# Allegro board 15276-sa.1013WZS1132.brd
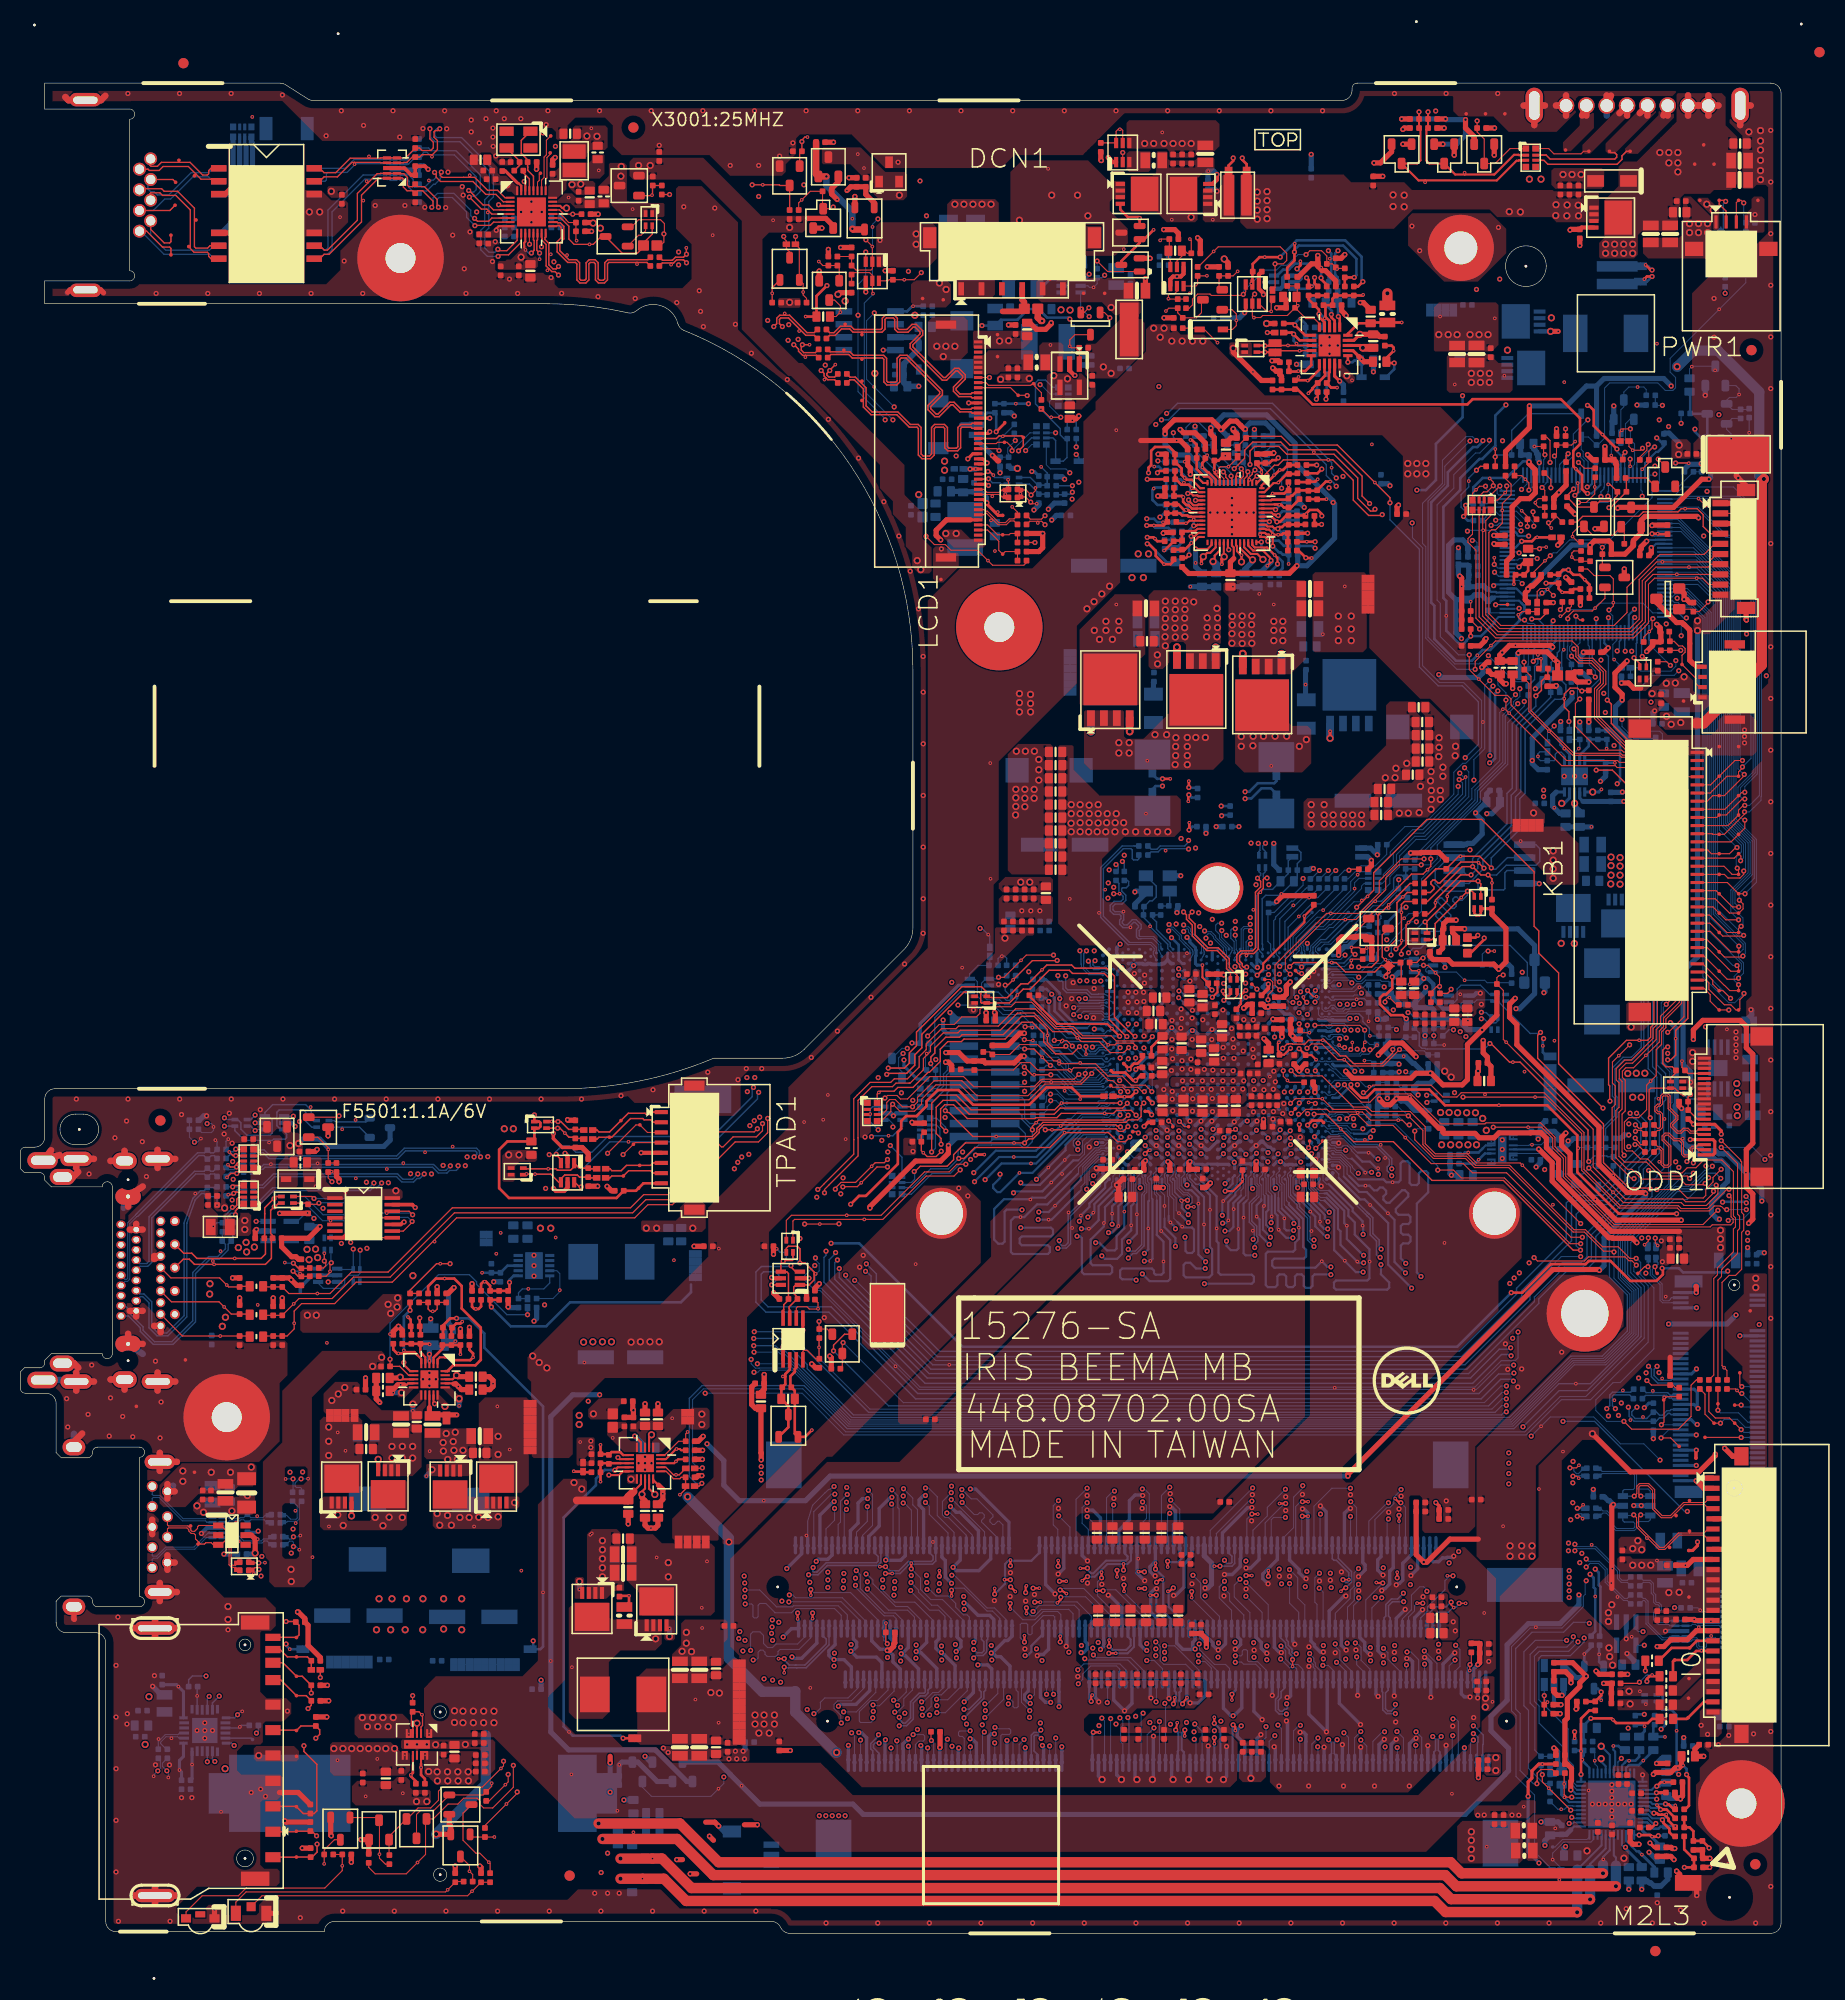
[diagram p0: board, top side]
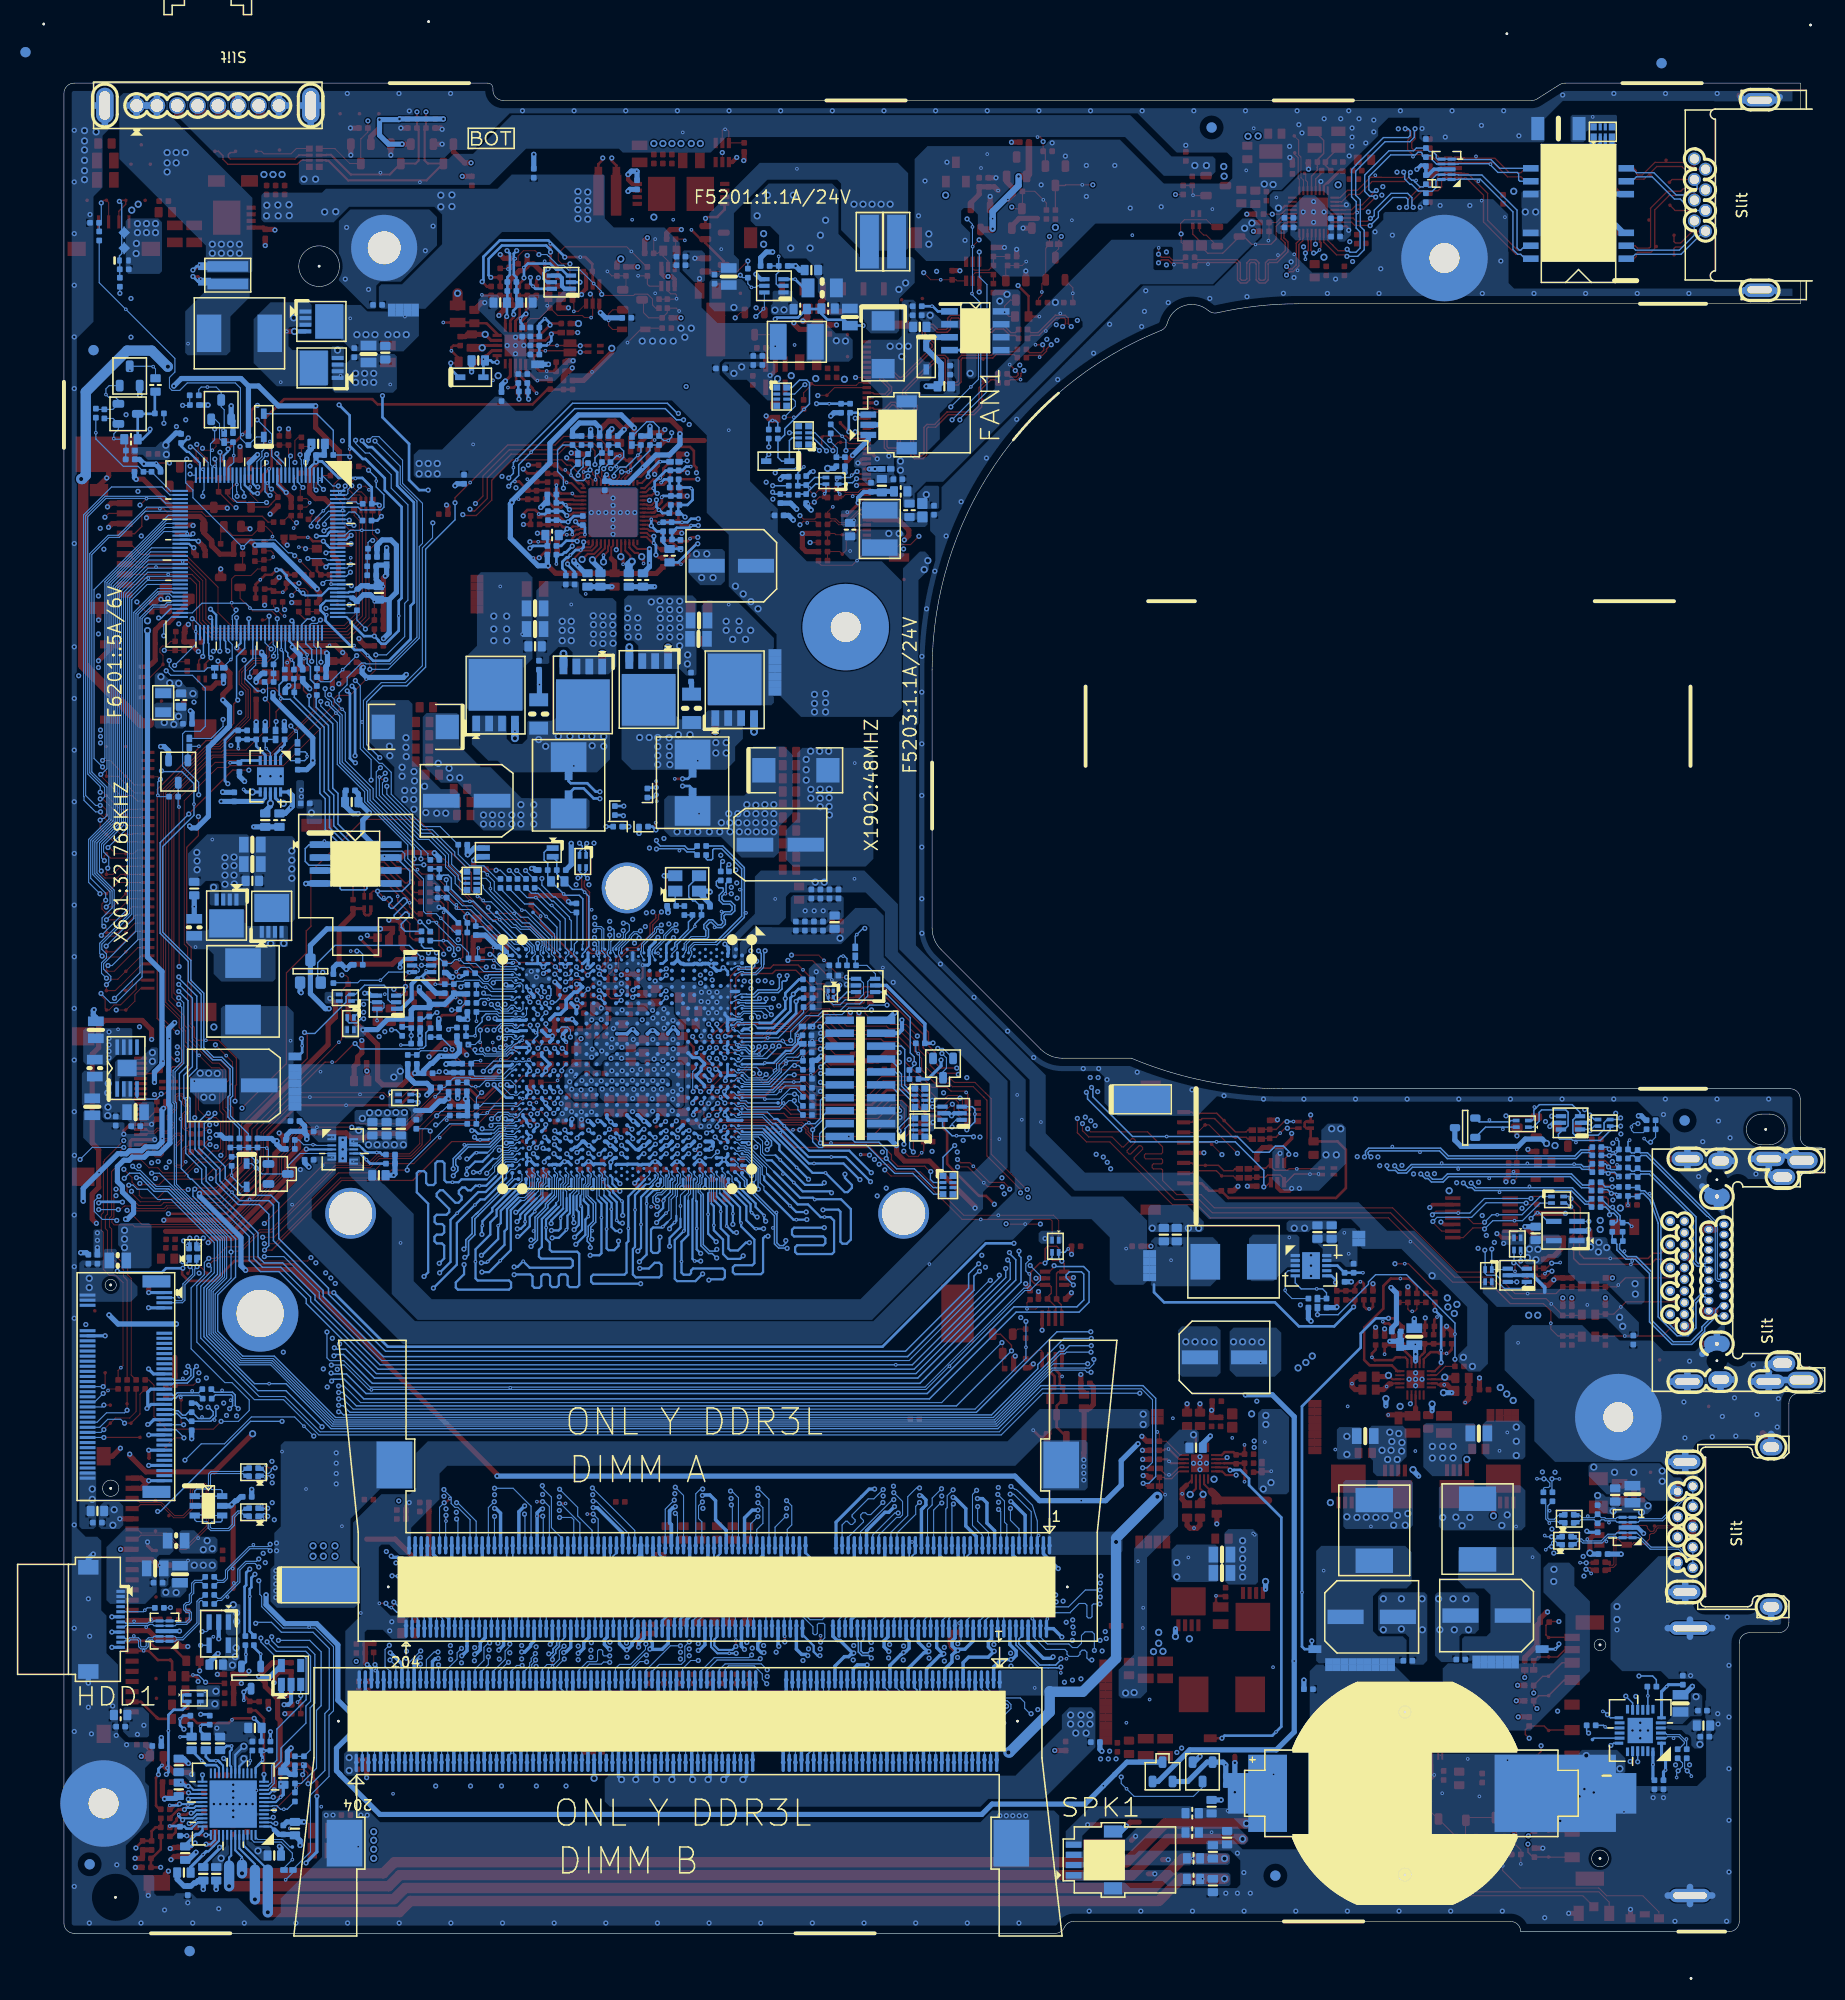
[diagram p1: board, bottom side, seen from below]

Outline 173.2 x 181.97 mm; copper layers: TOP, L2VCC, L3, L4, L5GND, BOTTOM. Coordinates in mm from the lower left corner of the outline.

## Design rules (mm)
constraint set DEFAULT: min track width 0.127, pair gap 0.102
net group APU_4_5: nets H_A20GATE PM_PWRBTN#_R
net group APU_4_8: nets PM_RSMRST# PM_RSMRST#_R
net group CLK: nets CLK_PCI_KBC CLK_PCI_LPC
net group CRT_SYNC_50-MW: nets CRT_HSYNC_CON CRT_VSYNC_CON
net group DDR_RST-MW: nets DDR3_DRAMRST# M_A_EVENT#
net group FAN_TACH: nets FAN_TACH1 FAN_TACH1_C
net group APU_4_12: nets APU_PWROK APU_PWROK_HDT APU_SIC APU_SID H_PROCHOT# H_PROCHOT#_EC PQ4008_6 PQ4405_3 PROCHOT_EC
net group APU_TEST_4: nets APU_TEST0 APU_TEST1 APU_TEST2 APU_TEST6_DIRECRACKMON APU_TEST14_BP0 APU_TEST15_BP1 APU_TEST16_BP2 APU_TEST17_BP3 APU_TEST18_PLLTEST1 APU_TEST19_PLLTEST0 APU_TEST28_H_PLLCHRZ APU_TEST28_L_PLLCHRZ APU_TEST31_M_TEST APU_TEST36_FREE_2 APU_TEST37_FREE_2 BYPASSCLK_H BYPASSCLK_L
net group APU_ZVSS: nets DP_2K_ZVSS DP_150_ZVSS M_ZVDDIO P_RX_ZVDD_095 P_TX_ZVDD_095 SATA_ZVDD_095 SATA_ZVSS USB_RCOMP USB_SS_ZVDD_095 USB_SS_ZVSS
net group AUDIO_BEEP: nets AUD_HP1_JACK_L AUD_HP1_JACK_L1 AUD_HP1_JACK_R AUD_HP1_JACK_R1 AUD_PC_BEEP AUD_PC_BEEP_C AUD_PORTA_L_R_B AUD_PORTA_R_R_B AUD_SENSE AUD_SENSE_A CBN CBP CPVEE HDA_SPKR HDA_SPKR_R JACK_PLUG KBC_BEEP KBC_BEEP_R LINE1-L_C LINE1-L_R LINE1_L LINE1_R LINE1_VREFO_L LINE1_VREFO_R MIC2_VREFO
net group AUDIO_BITCLK-MW: nets CODEC_BITCLK_R HDA_CODEC_BITCLK HDA_CODEC_BITCLK_R
net group AUDIO_DIGITAL-MW: nets CODEC_SDOUT_R HDA_CODEC_RST# HDA_CODEC_RST#_R HDA_CODEC_SDIN0 HDA_CODEC_SDOUT HDA_CODEC_SDOUT_R HDA_CODEC_SYNC HDA_CODEC_SYNC_R HDA_SDIN0
net group CARD_12MIL: nets RREF RSET SDREFG V18
net group CLK-REQ: nets CLK_LAN_REQ0#_R CLK_PCIE_LAN_REQ0# CLK_PCIE_WLAN_REQ1#
net group CR_50OHM-MW: nets SD_CD# SD_CD_R# SD_CLK SD_CLK_5170 SD_CMD SD_D0 SD_D1 SD_D2 SD_D3 SD_WP SD_WP_5170
net group CR_GPIO-MW: nets CR_GPIO0
net group CRT-MW: nets CRT_DDCCLK_CON_R CRT_DDCDATA_CON_R CRT_HSYNC1_1 CRT_VSYNC1_1 DAC_HSYNC DAC_SCL DAC_SDA DAC_VSYNC DAC_ZVSS
net group CRT-RGB-MW: nets DAC_BLUE DAC_GREEN DAC_RED
net group CRT_55-MW: nets CRT_B CRT_G CRT_R
net group DDR3_A_CMD: nets M_A_A0 M_A_A1 M_A_A2 M_A_A3 M_A_A4 M_A_A5 M_A_A6 M_A_A7 M_A_A8 M_A_A9 M_A_A10 M_A_A11 M_A_A12 M_A_A13 M_A_A14 M_A_A15 M_A_BS0 M_A_BS1 M_A_BS2 M_A_CAS# M_A_RAS# M_A_WE#
net group DDR3_A_CTRL: nets M_B_DIM0_CKE0 M_B_DIM0_CKE1 M_B_DIM0_CS#0 M_B_DIM0_CS#1 M_B_DIM0_ODT0 M_B_DIM0_ODT1
net group DDR3_A_DM: nets M_A_DM0 M_A_DM1 M_A_DM2 M_A_DM3 M_A_DM4 M_A_DM5 M_A_DM6 M_A_DM7 M_A_DQ<0> M_A_DQ<1> M_A_DQ<2> M_A_DQ<3> M_A_DQ<4> M_A_DQ<5> M_A_DQ<6> M_A_DQ<7> M_A_DQ<8> M_A_DQ<9> M_A_DQ<10> M_A_DQ<11> M_A_DQ<12> M_A_DQ<13> M_A_DQ<14> M_A_DQ<15> M_A_DQ<16> M_A_DQ<17> M_A_DQ<18> M_A_DQ<19> M_A_DQ<20> M_A_DQ<21> M_A_DQ<22> M_A_DQ<23> M_A_DQ<24> M_A_DQ<25> M_A_DQ<26> M_A_DQ<27> M_A_DQ<28> M_A_DQ<29> M_A_DQ<30> M_A_DQ<31> M_A_DQ<32> M_A_DQ<33> M_A_DQ<34> M_A_DQ<35> M_A_DQ<36> M_A_DQ<37> M_A_DQ<38> M_A_DQ<39> M_A_DQ<40> M_A_DQ<41> M_A_DQ<42> M_A_DQ<43> M_A_DQ<44> M_A_DQ<45> M_A_DQ<46> M_A_DQ<47> M_A_DQ<48> M_A_DQ<49> M_A_DQ<50> M_A_DQ<51> M_A_DQ<52> M_A_DQ<53> M_A_DQ<54> M_A_DQ<55> M_A_DQ<56> M_A_DQ<57> M_A_DQ<58> M_A_DQ<59> M_A_DQ<60> M_A_DQ<61> M_A_DQ<62> M_A_DQ<63>
net group DDR3_B_CTRL: nets M_A_DIM0_CKE0 M_A_DIM0_CKE1 M_A_DIM0_CS#0 M_A_DIM0_CS#1 M_A_DIM0_ODT0 M_A_DIM0_ODT1
net group GND: nets EC_AGND GND_R1 GND_R2 MIC_GND
net group HDT_APU: nets APU_DBRDY APU_DBREQ# APU_TCK APU_TDI APU_TDO APU_TMS APU_TRST# DBRDY1 DBRDY2 DBRDY3
net group JTAG_APU: nets APU_ALERT# APU_RST# APU_RST_L_BUF APU_SVC APU_SVD APU_SVT PWR_APU_SVC PWR_APU_SVD PWR_APU_SVT
net group KB: nets KCOL0 KCOL1 KCOL2 KCOL3 KCOL4 KCOL5 KCOL6 KCOL7 KCOL8 KCOL9 KCOL10 KCOL11 KCOL12 KCOL13 KCOL14 KCOL15 KCOL16 KROW0 KROW1 KROW2 KROW3 KROW4 KROW5 KROW6 KROW7
net group LCD_BKLT-MW: nets BKLT_CTRL EC_BRIGHTNESS EDP_BKLT_CTRL L_BKLT_CTRL LCD_BRIGHTNESS
net group LED: nets AMBER_LED_BAT BAT_AMBER BAT_WHITE BATT_WHITE_LED# BATT_WHITE_LED_R# CAP_LED CAP_LED# CAP_LED_Q CAP_LED_R# CHG_AMBER_LED# CHG_AMBER_LED_R# SATA_LED SATA_LED# SATA_LED#_B SATA_LED#_R SATA_LED_R WHITE_LED_BAT
net group LPC: nets APU_LPC_AD0 APU_LPC_AD1 APU_LPC_AD2 APU_LPC_AD3 INT_SERIRQ LPC_AD0 LPC_AD1 LPC_AD2 LPC_AD3 LPC_FRAME# LPC_FRAME#_DEBUG LPC_FRAME#_R LPC_LAD0_R LPC_LAD1_R LPC_LAD2_R LPC_LAD3_R
net group OTHER_4MIL: nets 51123_PGOOD_2 AC_IN# AC_IN_KBC# AC_PRESENT AD+_G_1 ALERT# AMP_MUTE# BAT_IN# BLINK BLON_OUT BLON_OUT_C BLUETOOTH_EN BLUETOOTH_EN_NGFF CARD_WLAN_OUT# CLK_PCIE_WLAN_REQ# COMBO-GPI DBC_EN DBC_EN_R DM2_SA0 E51_RX1 E51_RX2 E51_TX1 E51_TX2 E51_TXD EAPD# EC_SCI# EC_SMI# EC_SWI# ECRST# ECSCI#_KBC ECSMI#_KBC ECSWI#_KBC EDP_HPD EDP_HPD_CONN EDP_VDD_EN GEVENT4# GEVENT7# GPIO71 H_RCIN# HDD_DEVSLP HDD_DEVSLP_R HDMI_CRT_DET HDMI_HPD_B HDMI_HPD_E HPD_HDMI_CON INT_TP# IRIS_BEEMA_ID ISOLATE# JDREF KB_BL_CTRL KB_DET# KB_LED_BL_DET KB_LED_DET_C KBC_ON#_GATE KBC_ON#_GATE_L KBC_PWRBTN# L_BKLT_EN L_BKLT_EN_EC LCD_TST LCD_TST_C LCD_TST_EN LCDVDD_EN LDRQ0# LED0 LED1 LED2 LID_CLOSE# LID_CLOSE#_C LPC_PD# LPC_RST# LPC_RST#_C M_ANALOGIN M_ANALOGOUT MODEL_ID_DET PANEL_SIZE_ID PANEL_SIZE_ID_CONN PCB_VER_AD PD4403_A PD4403_K PLT_RST_NGFF# PM_CLKRUN#_EC PM_PWRBTN# PQ3808D PQ3808G PQ4203_5 PQ4405_2 PQ4405_5 PQ4405_6 PQ4408_C PQ4408_E PSID_EC PSL_IN1# PSL_IN2# PSL_OUT# PWR_CHG_ACOK PWR_CHG_AD_OFF PWR_CHG_AD_OFF_R PWR_CPU_EN Q402_1 Q603_2 Q6205_Q RTC_DET# SYS_RESET# TEMPINRETURN TP41 TP_LOCK# TP_LOCK#_R TP_ON# TP_ON#_GATE TP_ON#_S TP_RESET TP_RS TP_WAKE_KBC# USB_ATEST0 USB_ATEST1 VD1_EN# VRAM SIZE1 WIFI_RF_EN WLAN_DISABLE#1 WLAN_WAKE
net group OTHER_4MIL_2H: nets 0D95V_PWRGD 0D95V_S0_EN 0D95V_S5_PWRGD 1D8V_S5_PWRGD 1D35V_PGOOD DGPU_PRESENT# PM_SLP_S3#
net group OTHER_4MIL_3H: nets APU_RST#_C PLT_RST# PLT_RST#_EC
net group OTHER_5.5M: nets LPCCLK0 LPCCLK1 MEM_1V5 PCH_SUSCLK_KBC RTC_CLK
net group OTHER_10MIL: nets VDDIO_MEM_SENSE
net group PLATFORM: nets 0D95_S5_EN 1D5V_S0_EN 3D_VEDIO 3V5V_S0_ON 3V_5V_EN 3V_5V_POK AC_IN#_G ALL_SYS_PWRGD APU_DIGON APU_PWROK_C CLK_LAN_REQ#_EN DDR_VTT_PG_CTRL_R H_CPUPWRGD_REG IMVP_PWRGD KBC_PWRBTN#_C LAN_ENABLE_R_C PCIE_RST#_C PCIE_WAKE# PCIE_WAKE#_R PLT_RST#_DEBUG PLT_RST#_LAN PM_LAN_ENABLE PM_LAN_ENABLE_R PM_SLP_S5# PWR_0D95V_EN PWR_0D95V_PWRGD PWR_1D8V_EN PWR_1D35V_EN PWR_5V_EN1_R PWR_APU_VDD_PGOOD PWR_VDDNB_PGOOD PWROK RSMRST#_KBC RTC_1D5V_PWR RTC_1D5V_S5 RTCRST_ON RUNPWROK_D S0_PWR_GOOD_R S5_ENABLE SATA_ODD_DA# SATA_ODD_DA#_C SATA_ODD_PRSNT# SATA_ODD_PWRGT SYS_PWRGD TOUCH_PANEL_INTR# TOUCH_PANEL_INTR_KBC# USB_PWR_EN# V3D3_STB VCORE_EN
net group POWER_10M: nets 3V5V_CT1 3V5V_CT2 AD_IA AD_IA_HW AD_IA_HW2 BOOST_MODE# EC_VBKUP FAN1_DAC_1 MIC_CAP PQ4008_2 TP_VDD TPS51216_PHS_SET
net group POWER_10M_POWER: nets AD_OFF_L AD_OFF_R APU_VDDNB_RUN_FB_H COMPNB_R DIFFNB_R ILIM_R ILIMNB_R PQ3809_D PR4601_1 PWR_0D95V_CCM PWR_0D95V_FB PWR_0D95V_PWR PWR_0D95V_TRIP PWR_1D8V_FB PWR_1D8V_FB_A PWR_1D8V_SVIN PWR_1D35V_MODE PWR_1D35V_REFIN PWR_1D35V_TRIP PWR_1D35V_VREF PWR_3D3V_CS PWR_3D3V_EN2 PWR_3D3V_FB PWR_3D3V_FB_A PWR_3D3V_FB_B PWR_5V_CS PWR_5V_EN1 PWR_5V_FB PWR_5V_FB_A PWR_5V_VO PWR_APU_VDD_CSN1 PWR_APU_VDD_SWN1 PWR_CHG_ACDET PWR_CHG_BTST_R PWR_CHG_CMPIN PWR_CHG_CMPIN_R PWR_CHG_CMPIN_RR PWR_CHG_CMPOUT PWR_CHG_IFAULT PWR_CHG_ILIM PWR_CHG_IOUT PWR_CHG_REGN PWR_CHG_VCC PWR_COMP_R PWR_CPU_COMP PWR_CPU_COMPNB PWR_CPU_CSCOMP PWR_CPU_CSCOMPNB PWR_CPU_CSP1 PWR_CPU_CSP1NB PWR_CPU_CSP2 PWR_CPU_CSP2NB PWR_CPU_CSREF PWR_CPU_CSREFNB PWR_CPU_CSSUM PWR_CPU_CSSUMNB PWR_CPU_DIFF PWR_CPU_DIFFNB PWR_CPU_DROOP PWR_CPU_DROOPNB PWR_CPU_FB PWR_CPU_FBNB PWR_CPU_ILIM PWR_CPU_ILIMNB PWR_CPU_IOUT PWR_CPU_IOUTNB PWR_CPU_PHCONFIG PWR_CPU_ROSC PWR_CPU_SR PWR_CPU_TEENSE PWR_CPU_TSENSENB PWR_CPU_VCC PWR_CPU_VDD PWR_CPU_VDDNB PWR_CPU_VRMP PWR_CPU_VSS PWR_DIFF_R PWR_VDDNB_CSN1NB PWR_VDDNB_SWN1NB PWR_VDDQ_SENSE_APU PWR_VR_HOT VDD_095_FB_H VDD_095_FB_L VTT_CT_0.95V VTT_CT_1.8V
net group POWER_12M: nets +3V_1D5V_AVDD +3V_AVDD AUD_VREF LDO1_CAP LDO2_CAP LDO3_CAP
net group POWER_20M: nets 3D3V_AUX_KBC_VCC +RTC_VCC AD+_G_2 KB_BL_CTRL# MCT0 MCT1 MCT2 MCT3 PR4605_2 PWR_1D35V_VBST PWR_CHG_BTST RTC_AUX_S5 RTC_PWR VBAT
net group POWER_20M_POWER: nets 3D3V_PWR_2 3D3V_PWR_2_R 5V_PWR_2 5V_PWR_2_R PWR_0D95V_BOOT PWR_0D95V_BOOT_R PWR_1D05V_SNUB PWR_3D3V_BOOT PWR_3D3V_BOOT_A PWR_5V_BOOT PWR_5V_BOOT_A PWR_APU_VDD_BST1 PWR_APU_VDD_BST1_1 PWR_APU_VDD_SNUB PWR_VDDNB_BST2 PWR_VDDNB_BST2_1 PWR_VDDNB_SNUB
net group POWER_25MIL: nets PQ3802_1 PS_ID PS_ID_R PSID_DISABLE#_R_C
net group POWER_30M_POWER: nets PWR_APU_VDD_HG1 PWR_APU_VDD_LG1 PWR_VDDNB_HG2 PWR_VDDNB_LG2
net group POWER_40M: nets 1D5V_S0 3D3V_CAMERA_S0 FAN_VCC1
net group POWER_40M_POWER: nets PWR_CHG_HIDRV
net group REF10M: nets KBC_VCORF
net group SPI-MWS: nets APU_SPI_CLK APU_SPI_CS0# APU_SPI_HOLD# APU_SPI_SI_R APU_SPI_SO_R APU_SPI_WP# EC_SPI_CLK_C EC_SPI_CS#_C EC_SPI_DI_C EC_SPI_DO_C SPI_CLK_R SPI_CS0#_R SPI_CS2# SPI_HOLD# SPI_SI_R SPI_SO_R SPI_SW SPI_WP#
net group T8: nets VD_IN1 VD_IN1_C VD_OUT1#
net group THERM_10M: nets FON#
net group THERM_SHUTDOWN: nets PURE_HW_SHUTDOWN# T_CRIT# THERM_SYS_SHDN#
net group USB_OC: nets USB_OC#0 USB_OC#1 USB_OC#3
net group XTAL-MWS: nets 32K_X1 32K_X2 48M_X1 48M_X2 LANXIN LANXOUT LANXOUT.R R1930.R
nets with their own width: min track width 0.508; nets GND

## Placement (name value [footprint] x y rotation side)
AFTP2501  AFTE14P-GP  [AFTE14P-75]  67.42 10.93 0 top
AFTP2502  AFTE14P-GP  [AFTE14P-75]  58.02 17.41 270 top
AFTP2801  AFTE14P-GP  [AFTE14P-75]  96.25 144.82 180 top
AFTP2802  AFTE14P-GP  [AFTE14P-75]  96.83 148.58 180 top
AFTP2803  AFTE14P-GP  [AFTE14P-75]  90.56 133.16 0 top
AFTP2901  AFTE14P-GP  [AFTE14P-75]  71.23 10.68 0 top
AFTP2902  AFTE14P-GP  [AFTE14P-75]  68.18 9.15 0 top
AFTP2903  AFTE14P-GP  [AFTE14P-75]  65.13 7.25 0 top
AFTP2904  AFTE14P-GP  [AFTE14P-75]  66.53 5.85 0 top
AFTP3101  AFTE14P-GP  [AFTE14P-75]  15.22 169.96 90 top
AFTP3102  AFTE14P-GP  [AFTE14P-75]  14.82 167.02 90 top
AFTP3103  AFTE14P-GP  [AFTE14P-75]  16.57 165.9 90 top
AFTP3104  AFTE14P-GP  [AFTE14P-75]  17.28 168.51 90 top
AFTP3105  AFTE14P-GP  [AFTE14P-75]  17.13 172.86 90 top
AFTP3106  AFTE14P-GP  [AFTE14P-75]  15.27 172.22 90 top
AFTP3107  AFTE14P-GP  [AFTE14P-75]  14.82 165.09 90 top
AFTP3108  AFTE14P-GP  [AFTE14P-75]  15.6 174.38 90 top
AFTP3301  AFTE14P-GP  [AFTE14P-75]  11.41 51.83 0 top
AFTP3302  AFTE14P-GP  [AFTE14P-75]  27.16 12.46 0 top
AFTP3303  AFTE14P-GP  [AFTE14P-75]  27.16 19.95 0 top
AFTP3304  AFTE14P-GP  [AFTE14P-75]  27.16 27.19 0 top
AFTP3305  AFTE14P-GP  [AFTE14P-75]  27.16 29.09 0 top
AFTP3306  AFTE14P-GP  [AFTE14P-75]  27.16 23.38 0 top
AFTP3307  AFTE14P-GP  [AFTE14P-75]  27.16 25.28 0 top
AFTP3308  AFTE14P-GP  [AFTE14P-75]  27.16 7.5 0 top
AFTP3309  AFTE14P-GP  [AFTE14P-75]  27.16 10.04 0 top
AFTP3310  AFTE14P-GP  [AFTE14P-75]  27.16 17.41 0 top
AFTP3401  AFTE14P-GP  [AFTE14P-75]  17.13 45.35 0 top
AFTP3402  AFTE14P-GP  [AFTE14P-75]  16.75 40.07 0 top
AFTP3403  AFTE14P-GP  [AFTE14P-75]  17.48 38.29 0 top
AFTP3801  AFTE14P-GP  [AFTE14P-75]  88.75 160.79 0 top
AFTP3802  AFTE14P-GP  [AFTE14P-75]  96.63 159.52 90 top
AFTP3803  AFTE14P-GP  [AFTE14P-75]  104.59 161.31 0 top
AFTP3805  AFTE14P-GP  [AFTE14P-75]  90.79 160.67 0 top
AFTP3806  AFTE14P-GP  [AFTE14P-75]  106.66 161.3 0 top
AFTP3901  AFTE14P-GP  [AFTE14P-75]  152 175.4 0 top
AFTP3902  AFTE14P-GP  [AFTE14P-75]  154.29 175.27 0 top
AFTP3903  AFTE14P-GP  [AFTE14P-75]  156.32 175.27 0 top
AFTP3904  AFTE14P-GP  [AFTE14P-75]  158.35 175.27 0 top
AFTP3905  AFTE14P-GP  [AFTE14P-75]  164.7 174 0 top
AFTP3906  AFTE14P-GP  [AFTE14P-75]  144.13 178.95 0 top
AFTP3907  AFTE14P-GP  [AFTE14P-75]  165.59 175.91 0 top
AFTP3908  AFTE14P-GP  [AFTE14P-75]  166.61 174 0 top
AFTP3909  AFTE14P-GP  [AFTE14P-75]  142.22 178.95 0 top
AFTP3910  AFTE14P-GP  [AFTE14P-75]  146.03 178.95 0 top
AFTP5201  AFTE14P-GP  [AFTE14P-75]  99.68 152.41 0 top
AFTP5202  AFTE14P-GP  [AFTE14P-75]  96.12 155.08 0 top
AFTP5203  AFTE14P-GP  [AFTE14P-75]  98.66 147.13 0 top
AFTP5204  AFTE14P-GP  [AFTE14P-75]  96.12 157.24 0 top
AFTP5205  AFTE14P-GP  [AFTE14P-75]  96.81 146.65 0 top
AFTP5206  AFTE14P-GP  [AFTE14P-75]  81.13 158.25 0 top
AFTP5207  AFTE14P-GP  [AFTE14P-75]  98.15 151.27 0 top
AFTP5208  AFTE14P-GP  [AFTE14P-75]  82.79 157.24 0 top
AFTP5209  AFTE14P-GP  [AFTE14P-75]  96.63 137.55 90 top
AFTP5210  AFTE14P-GP  [AFTE14P-75]  82.79 154.82 0 top
AFTP5211  AFTE14P-GP  [AFTE14P-75]  82.79 152.66 0 top
AFTP5212  AFTE14P-GP  [AFTE14P-75]  82.79 150.76 0 top
AFTP5213  AFTE14P-GP  [AFTE14P-75]  81.01 155.71 0 top
AFTP5214  AFTE14P-GP  [AFTE14P-75]  96.63 135.65 0 top
AFTP5227  AFTE14P-GP  [AFTE14P-75]  96.63 139.46 0 top
AFTP5601  AFTE14P-GP  [AFTE14P-75]  164.12 37.65 0 top
AFTP5801  AFTE14P-GP  [AFTE14P-75]  170.16 61.22 0 top
AFTP5802  AFTE14P-GP  [AFTE14P-75]  161.65 52.46 0 top
AFTP5803  AFTE14P-GP  [AFTE14P-75]  168.64 50.18 0 top
AFTP5804  AFTE14P-GP  [AFTE14P-75]  166.61 50.18 0 top
AFTP5805  AFTE14P-GP  [AFTE14P-75]  166.99 52.08 0 top
AFTP5806  AFTE14P-GP  [AFTE14P-75]  159.11 64.91 0 top
AFTP5807  AFTE14P-GP  [AFTE14P-75]  161.02 64.91 0 top
AFTP6101  AFTE14P-GP  [AFTE14P-75]  167.11 170.44 0 top
AFTP6102  AFTE14P-GP  [AFTE14P-75]  170.92 170.44 0 top
AFTP6103  AFTE14P-GP  [AFTE14P-75]  165.21 170.44 0 top
AFTP6104  AFTE14P-GP  [AFTE14P-75]  169.02 170.44 0 top
AFTP6201  AFTE14P-GP  [AFTE14P-75]  169.02 116.72 0 top
AFTP6202  AFTE14P-GP  [AFTE14P-75]  167.11 90.82 0 top
AFTP6203  AFTE14P-GP  [AFTE14P-75]  167.11 109.99 0 top
AFTP6206  AFTE14P-GP  [AFTE14P-75]  169.02 104.15 0 top
AFTP6207  AFTE14P-GP  [AFTE14P-75]  167.11 106.18 0 top
AFTP6208  AFTE14P-GP  [AFTE14P-75]  167.11 104.15 0 top
AFTP6213  AFTE14P-GP  [AFTE14P-75]  169.02 100.34 0 top
AFTP6214  AFTE14P-GP  [AFTE14P-75]  169.02 94.63 0 top
AFTP6215  AFTE14P-GP  [AFTE14P-75]  169.02 98.44 0 top
AFTP6216  AFTE14P-GP  [AFTE14P-75]  169.02 111.9 0 top
AFTP6217  AFTE14P-GP  [AFTE14P-75]  16.24 56.4 0 top
AFTP6218  AFTE14P-GP  [AFTE14P-75]  167.11 94.63 0 top
AFTP6219  AFTE14P-GP  [AFTE14P-75]  167.11 111.9 0 top
AFTP6220  AFTE14P-GP  [AFTE14P-75]  169.02 113.8 0 top
AFTP6221  AFTE14P-GP  [AFTE14P-75]  169.02 90.82 0 top
AFTP6222  AFTE14P-GP  [AFTE14P-75]  167.11 92.72 0 top
AFTP6223  AFTE14P-GP  [AFTE14P-75]  167.11 102.25 0 top
AFTP6224  AFTE14P-GP  [AFTE14P-75]  167.11 100.34 0 top
AFTP6225  AFTE14P-GP  [AFTE14P-75]  167.11 108.09 0 top
AFTP6226  AFTE14P-GP  [AFTE14P-75]  169.02 106.18 0 top
AFTP6227  AFTE14P-GP  [AFTE14P-75]  167.11 96.53 0 top
AFTP6228  AFTE14P-GP  [AFTE14P-75]  167.11 98.44 0 top
AFTP6229  AFTE14P-GP  [AFTE14P-75]  169.02 109.99 0 top
AFTP6230  AFTE14P-GP  [AFTE14P-75]  169.02 92.72 0 top
AFTP6231  AFTE14P-GP  [AFTE14P-75]  169.02 102.25 0 top
AFTP6232  AFTE14P-GP  [AFTE14P-75]  167.11 113.8 0 top
AFTP6233  AFTE14P-GP  [AFTE14P-75]  169.02 108.09 0 top
AFTP6234  AFTE14P-GP  [AFTE14P-75]  169.02 96.53 0 top
AFTP6235  AFTE14P-GP  [AFTE14P-75]  164.83 63.64 0 top
AFTP6236  AFTE14P-GP  [AFTE14P-75]  57.95 78.3 0 top
AFTP6237  AFTE14P-GP  [AFTE14P-75]  60.92 75.53 0 top
AFTP6238  AFTE14P-GP  [AFTE14P-75]  59.08 79.94 0 top
AFTP6239  AFTE14P-GP  [AFTE14P-75]  60.81 73.29 0 top
AFTP6240  AFTE14P-GP  [AFTE14P-75]  59.32 74.49 0 top
AFTP6241  AFTE14P-GP  [AFTE14P-75]  60.31 77.61 0 top
AFTP6242  AFTE14P-GP  [AFTE14P-75]  60.94 79.51 0 top
AFTP6245  AFTE14P-GP  [AFTE14P-75]  167.11 116.72 0 top
AFTP6246  AFTE14P-GP  [AFTE14P-75]  163.46 124.79 0 top
AFTP6247  AFTE14P-GP  [AFTE14P-75]  164.22 126.86 0 top
AFTP6248  AFTE14P-GP  [AFTE14P-75]  163.61 121.19 0 top
AFTP6301  AFTE14P-GP  [AFTE14P-75]  164.19 42.56 0 top
AFTP6302  AFTE14P-GP  [AFTE14P-75]  162.87 41.08 0 top
AFTP6303  AFTE14P-GP  [AFTE14P-75]  162.24 37.96 0 top
AFTP6304  AFTE14P-GP  [AFTE14P-75]  164.19 39.56 0 top
AFTP6305  AFTE14P-GP  [AFTE14P-75]  164.09 23.12 0 top
AFTP6306  AFTE14P-GP  [AFTE14P-75]  164.21 28.07 0 top
AFTP6307  AFTE14P-GP  [AFTE14P-75]  164.07 21.22 0 top
AFTP6309  AFTE14P-GP  [AFTE14P-75]  162.72 26.88 0 top
AFTP6310  AFTE14P-GP  [AFTE14P-75]  164.14 25.06 0 top
AFTP6311  AFTE14P-GP  [AFTE14P-75]  164.14 33.08 0 top
AFTP6313  AFTE14P-GP  [AFTE14P-75]  162.49 28.88 0 top
AFTP6314  AFTE14P-GP  [AFTE14P-75]  164.83 46.75 90 top
BATT1  SYN-CON8-9-GP-U  [200277MR008G121ZR-U]  159.05 179.77 0 bottom
C1  HOLE197R166-1-GP  [HOLE197R166]  145 70.82 180 bottom
C2  HOLE197R166-1-GP  [HOLE197R166]  90.6 70.82 180 bottom
C3  HOLE197R166-1-GP  [HOLE197R166]  117.8 102.82 180 bottom
C303  SCD1U16V2KX-3GP  [C402H22]  110.47 106.94 270 bottom
C304  SCD1U16V2KX-3GP  [C402H22]  110.47 106.06 270 bottom
C305  SCD1U16V2KX-3GP  [C402H22]  107.78 104 0 bottom
C306  SCD1U16V2KX-3GP  [C402H22]  108.59 104 0 bottom
C401  SC150P50V2KX-GP  [C402H22]  88.96 87.54 90 bottom
C402  SC150P50V2KX-GP  [C402H22]  97.47 95.21 270 bottom
C443  SCD1U16V2KX-3GP  [C402H22]  97.47 94.19 90 bottom
C501  SCD1U10V2KX-5GP  [C402H22]  107.39 75.64 0 top
C502  SC1KP50V2KX-1GP  [C402H22]  106.5 75.64 0 top
C601  SC150P50V2KX-GP  [C402H22]  134.35 90.43 0 bottom
C603  SC15P50V2JN-2-GP  [C402H22]  124.28 104.57 90 bottom
C604  SC15P50V2JN-2-GP  [C402H22]  126.06 104.57 270 bottom
C701  SC1U10V3KX-3GP  [C603H36]  135.84 92.95 0 top
C702  SC1U10V3KX-3GP  [C603H36]  137.11 92.95 0 top
C703  SC10U6D3V3MX-GP  [C603H38]  114.99 92.22 180 top
C704  SC1U6D3V2KX-GP  [C402H22]  117.51 90.84 0 top
C705  SC1U10V3KX-3GP  [C603H36]  140.57 97.67 270 top
C762  SC10U6D3V3MX-GP  [C603H38]  116.29 91.73 180 top
C1001  SC1U10V2KX-1GP  [C402H22]  124.54 89.87 90 top
C1002  SC1U10V2KX-1GP  [C402H22]  139.11 96.53 90 top
C1003  SC180P50V2JN-1GP  [C402H22]  97.01 102.22 180 bottom
C1004  SC1U6D3V2KX-GP  [C402H22]  99.68 102.22 0 top
C1005  SC1U6D3V2KX-GP  [C402H22]  99.68 102.22 180 bottom
C1006  SC1U6D3V2KX-GP  [C402H22]  98.79 102.22 180 bottom
C1007  SC1U6D3V2KX-GP  [C402H22]  97.01 102.22 0 top
C1008  SC1U6D3V2KX-GP  [C402H22]  97.9 102.22 0 top
C1009  SC1U6D3V2KX-GP  [C402H22]  98.79 102.22 0 top
C1010  SC4D7U6D3V3KX-GP  [C603H36]  100.88 102.3 0 top
C1011  SC180P50V2JN-1GP  [C402H22]  97.9 102.22 180 bottom
C1012  SC1U6D3V2KX-GP  [C402H22]  121.62 90.5 270 top
C1013  SC1U6D3V2KX-GP  [C402H22]  120.78 88.72 0 top
C1014  SC1U6D3V2KX-GP  [C402H22]  119.96 88.72 0 top
C1015  SC4D7U6D3V3KX-GP  [C603H36]  142.32 90.31 180 top
C1016  SC4D7U6D3V3KX-GP  [C603H36]  141.05 90.31 180 top
C1017  SCD1U10V2KX-4GP  [C402H20]  95.46 89.77 270 top
C1022  SC180P50V2JN-1GP  [C402H22]  124.54 88.98 90 top
C1023  SC1U10V2KX-1GP  [C402H22]  122.86 88.98 270 top
C1024  SC1U10V2KX-1GP  [C402H22]  134.86 85.1 180 bottom
C1025  SC180P50V2JN-1GP  [C402H22]  101.2 99.07 0 bottom
C1026  SC1U6D3V2KX-GP  [C402H22]  100.31 99.07 0 bottom
C1027  SC1U6D3V2KX-GP  [C402H22]  98.53 99.07 180 top
C1028  SC1U6D3V2KX-GP  [C402H22]  99.42 99.07 180 top
C1029  SC1U6D3V2KX-GP  [C402H22]  99.42 99.07 0 bottom
C1030  SC1U6D3V2KX-GP  [C402H22]  98.53 99.07 0 bottom
C1031  SC1U6D3V2KX-GP  [C402H22]  96.76 99.07 180 top
C1032  SC1U6D3V2KX-GP  [C402H22]  97.64 99.07 180 top
C1033  SC4D7U6D3V3KX-GP  [C603H36]  97.39 99.45 0 bottom
C1034  SC180P50V2JN-1GP  [C402H22]  123.4 91.63 180 top
C1035  SC1U6D3V2KX-GP  [C402H22]  121.62 91.36 270 top
C1036  SC1U6D3V2KX-GP  [C402H22]  143.87 85.61 90 top
C1037  SC1U6D3V2KX-GP  [C402H22]  124.24 91.63 180 top
C1038  SC4D7U6D3V3KX-GP  [C603H36]  144 83.83 90 top
C1039  SC180P50V2JN-1GP  [C402H22]  121.11 81.89 0 top
C1040  SC1U6D3V2KX-GP  [C402H22]  122 81.89 0 top
C1041  SC1U6D3V2KX-GP  [C402H22]  122.81 81.89 0 top
C1042  SC1U6D3V2KX-GP  [C402H22]  123.62 81.89 0 top
C1043  SC1U6D3V2KX-GP  [C402H22]  120.48 84.57 270 top
C1044  SC1U6D3V2KX-GP  [C402H22]  121.72 85.02 180 top
C1045  SC1U6D3V2KX-GP  [C402H22]  125.31 85.94 0 top
C1046  SC4D7U6D3V3KX-GP  [C603H36]  140.06 79.13 0 bottom
C1047  SC22U6D3V3MX-1-GP  [C603H40]  142.86 79.13 0 bottom
C1049  SC180P50V2JN-1GP  [C402H22]  110.07 75.09 90 top
C1050  SC180P50V2JN-1GP  [C402H22]  116.21 75.14 270 top
C1051  SC180P50V2JN-1GP  [C402H22]  107.04 25.03 0 top
C1053  SC4D7U6D3V3KX-GP  [C603H36]  126.6 74.76 90 top
C1054  SC4D7U6D3V3KX-GP  [C603H36]  126.6 72.43 90 top
C1055  SC4D7U6D3V3KX-GP  [C603H36]  108.69 72.43 270 top
C1056  SCD1U10V2KX-4GP  [C402H20]  116.31 73.8 180 top
C1057  SCD1U10V2KX-4GP  [C402H20]  124.41 79.83 270 top
C1058  SCD1U10V2KX-4GP  [C402H20]  122.71 79.34 90 top
C1059  SCD1U10V2KX-4GP  [C402H20]  122 75.13 90 top
C1060  SCD1U10V2KX-4GP  [C402H20]  111.74 73.8 0 top
C1061  SCD1U10V2KX-4GP  [C402H20]  114.5 75.13 270 top
C1062  SCD1U10V2KX-4GP  [C402H20]  112.63 75.07 270 top
C1063  SCD1U10V2KX-4GP  [C402H20]  111.82 79.77 90 top
C1064  SC22U6D3V3MX-1-GP  [C603H40]  112.07 92.04 270 top
C1065  SC22U6D3V3MX-1-GP  [C603H40]  111.46 90.71 270 top
C1066  SC22U6D3V3MX-1-GP  [C603H40]  137.93 116.52 90 top
C1067  SC180P50V2JN-1GP  [C402H22]  115.2 94.35 90 top
C1068  SC22U6D3V3MX-1-GP  [C603H40]  137.93 115.25 90 top
C1069  SC22U6D3V3MX-1-GP  [C603H40]  114.23 87.54 0 top
C1070  SC22U6D3V3MX-1-GP  [C603H40]  116.16 87.26 0 top
C1071  SC22U6D3V3MX-1-GP  [C603H40]  112.35 87.59 0 top
C1072  SC22U6D3V3MX-1-GP  [C603H40]  118.22 88.76 180 top
C1073  SC22U6D3V3MX-1-GP  [C603H40]  111.72 89.42 270 top
C1074  SC22U6D3V3MX-1-GP  [C603H40]  137.55 120.58 90 top
C1075  SC22U6D3V3MX-1-GP  [C603H40]  137.9 119.14 90 top
C1077  SC22U6D3V3MX-1-GP  [C603H40]  114.41 81.42 0 top
C1080  SC180P50V2JN-1GP  [C402H22]  115.81 85.23 180 top
C1081  SC22U6D3V3MX-1-GP  [C603H40]  119.57 81.39 0 top
C1082  SC22U6D3V3MX-1-GP  [C603H40]  101.84 109.74 270 top
C1083  SC22U6D3V3MX-1-GP  [C603H40]  101.84 105.9 270 top
C1084  SC22U6D3V3MX-1-GP  [C603H40]  101.84 107.2 270 top
C1085  SC22U6D3V3MX-1-GP  [C603H40]  101.84 108.47 270 top
C1086  SC22U6D3V3MX-1-GP  [C603H40]  112.33 85.15 180 top
C1087  SC22U6D3V3MX-1-GP  [C603H40]  101.84 114.9 270 top
C1088  SC22U6D3V3MX-1-GP  [C603H40]  116.29 81.37 0 top
C1089  SC22U6D3V3MX-1-GP  [C603H40]  118.27 81.37 0 top
C1090  SC22U6D3V3MX-1-GP  [C603H40]  112.35 81.42 0 top
C1092  SC180P50V2JN-1GP  [C402H22]  139.05 89.93 0 top
C1093  SC1U6D3V2KX-GP  [C402H22]  137.27 89.93 180 top
C1094  SC1U6D3V2KX-GP  [C402H22]  121.59 88.72 0 top
C1095  SC1U6D3V2KX-GP  [C402H22]  139.94 89.93 180 top
C1096  SC1U6D3V2KX-GP  [C402H22]  138.16 89.93 180 top
C1097  SC22U6D3V3MX-1-GP  [C603H40]  101.84 113.6 270 top
C1098  SC22U6D3V3MX-1-GP  [C603H40]  101.84 112.3 270 top
C1099  SC22U6D3V3MX-1-GP  [C603H40]  101.84 111.01 270 top
C1100  SC22U6D3V3MX-1-GP  [C603H40]  101.84 104.61 270 top
C1101  SC22U6D3V3MX-1-GP  [C603H40]  101.84 116.19 270 top
C1105  SC22U6D3V3MX-1-GP  [C603H40]  136.96 113.96 90 top
C1106  SC22U6D3V3MX-1-GP  [C603H40]  137.93 117.84 90 top
C1107  SC22U6D3V3MX-1-GP  [C603H40]  117.43 86.4 0 top
C1113  SC22U6D3V3MX-1-GP  [C603H40]  134.2 112.56 90 top
C1114  SC22U6D3V3MX-1-GP  [C603H40]  133.87 111.26 90 top
C1115  SC22U6D3V3MX-1-GP  [C603H40]  133.87 109.99 90 top
C1201  SCD1U10V2KX-5GP  [C402H22]  137.75 41.49 90 top
C1202  SC2D2U6D3V2MX-GP  [C402H22]  137.75 42.38 90 top
C1203  SC1KP50V2KX-1GP  [C402H22]  116.14 29.93 180 top
C1204  SCD1U10V2KX-5GP  [C402H22]  59.8 52.33 90 top
C1205  SC1KP50V2KX-1GP  [C402H22]  115.25 29.93 180 top
C1208  SC10U6D3V3MX-GP  [C603H38]  139.35 31.02 270 top
C1209  SC1U6D3V2KX-GP  [C402H22]  139.35 32.17 270 top
C1210  SC1U6D3V2KX-GP  [C402H22]  140.01 41.64 90 top
C1211  SC1U6D3V2KX-GP  [C402H22]  140.01 40.75 90 top
C1212  SC1U6D3V2KX-GP  [C402H22]  139.35 33.06 270 top
C1213  SC4D7U6D3V3KX-L-GP  [C603H36]  112.25 39.38 180 top
C1214  SCD1U10V2KX-5GP  [C402H22]  114.15 25.03 180 top
C1215  SC4D7U6D3V3KX-GP  [C603H36]  110.6 39.38 180 top
C1216  SC4D7U6D3V3KX-GP  [C603H36]  107.42 39.38 180 top
C1217  SCD1U10V2KX-5GP  [C402H22]  108.57 19.57 180 top
C1218  SC4D7U6D3V3KX-GP  [C603H36]  113.9 39.38 180 top
C1219  SC4D7U6D3V3KX-GP  [C603H36]  105.9 39.38 180 top
C1220  SC4D7U6D3V3KX-GP  [C603H36]  108.95 39.38 180 top
C1221  SC1KP50V2KX-1GP  [C402H22]  85.58 29.6 90 top
C1222  SCD1U10V2KX-5GP  [C402H22]  109.96 19.57 180 top
C1223  SCD1U10V2KX-5GP  [C402H22]  115.81 25.03 180 top
C1224  SCD1U10V2KX-5GP  [C402H22]  112.63 25.03 180 top
C1225  SCD1U10V2KX-5GP  [C402H22]  105.77 25.03 180 top
C1306  SC2D2U6D3V2MX-GP  [C402H22]  144 27.57 90 top
C1307  SC1KP50V2KX-1GP  [C402H22]  122.03 18.3 180 top
C1326  SC4D7U6D3V3KX-GP  [C603H36]  112.25 31.25 0 top
C1327  SC4D7U6D3V3KX-GP  [C603H36]  106.03 31.25 0 top
C1328  SC4D7U6D3V3KX-GP  [C603H36]  107.68 31.25 0 top
C1329  SC4D7U6D3V3KX-GP  [C603H36]  113.9 31.25 0 top
C1330  SCD1U10V2KX-5GP  [C402H22]  109.84 25.03 180 top
C1331  SC10U6D3V3MX-GP  [C603H38]  139.35 29.53 270 top
C1332  SC4D7U6D3V3KX-L-GP  [C603H36]  110.73 31.25 0 top
C1333  SC1KP50V2KX-1GP  [C402H22]  90.02 19.82 90 top
C1334  SCD1U10V2KX-5GP  [C402H22]  144 28.46 90 top
C1335  SCD1U10V2KX-5GP  [C402H22]  118.4 19.57 180 top
C1336  SCD1U10V2KX-5GP  [C402H22]  121.14 18.3 180 top
C1337  SCD1U10V2KX-5GP  [C402H22]  116.57 19.57 180 top
C1338  SC1U6D3V2KX-GP  [C402H22]  143.87 17.03 270 top
C1339  SC1U6D3V2KX-GP  [C402H22]  143.75 24.78 270 top
C1340  SC1U6D3V2KX-GP  [C402H22]  143.87 16.14 270 top
C1341  SC1U6D3V2KX-GP  [C402H22]  143.75 23.89 270 top
C1342  SCD1U10V2KX-5GP  [C402H22]  108.44 25.03 180 top
C1343  SC4D7U6D3V3KX-GP  [C603H36]  109.2 31.25 0 top
C1344  SCD1U10V2KX-5GP  [C402H22]  111.23 25.03 180 top
C1345  SC1KP50V2KX-1GP  [C402H22]  120.25 18.3 180 top
C1346  SCD1U10V2KX-5GP  [C402H22]  112.5 19.57 180 top
C1904  SC6D8P50V2DN-GP  [C402H22]  110.09 100.98 270 bottom
C1905  SC6D8P50V2DN-GP  [C402H22]  113.42 101.05 90 bottom
C2402  SCD1U10V2KX-5GP  [C402H22]  142.22 129.17 90 top
C2403  SCD1U10V2KX-5GP  [C402H22]  142.92 134.46 270 bottom
C2404  SCD1U10V2KX-5GP  [C402H22]  143.36 132.09 0 bottom
C2405  SC2D2U10V3KX-1GP  [C603H36]  142.22 131.84 0 bottom
C2406  SCD1U10V2KX-5GP  [C402H22]  146.03 137.04 180 top
C2407  SCD1U10V2KX-5GP  [C402H22]  149.71 123.84 180 bottom
C2408  SCD1U10V2KX-5GP  [C402H22]  155.43 144.92 90 top
C2409  SCD1U10V2KX-5GP  [C402H22]  159.75 135.52 270 top
C2410  SCD1U10V2KX-5GP  [C402H22]  155.05 125.99 270 top
C2411  SC2D2U10V3KX-1GP  [C603H36]  146.79 124.47 0 top
C2412  SCD1U10V2KX-5GP  [C402H22]  148.85 145.38 270 bottom
C2413  SC2D2U10V3KX-1GP  [C603H36]  148.19 146.49 270 bottom
C2414  SCD1U10V2KX-5GP  [C402H22]  142.22 128.28 90 top
C2415  SC220P50V2KX-3GP  [C402H22]  150.4 140.27 270 top
C2416  SC1U6D3V2KX-GP  [C402H22]  162.03 138.06 180 top
C2417  SCD1U10V2KX-5GP  [C402H22]  158.22 136.66 90 top
C2418  SC1U6D3V2KX-GP  [C402H22]  153.03 124.8 270 bottom
C2421  SC47P50V2JN-3GP  [C402H22]  160.36 150.31 90 bottom
C2501  SC10U6D3V3MX-GP  [C603H38]  144.89 111.26 270 bottom
C2502  SCD1U10V2KX-5GP  [C402H22]  145.02 112.41 270 bottom
C2503  SCD47U6D3V2KX-GP  [C402H22]  140.44 98.82 90 top
C2601  SC10U6D3V3MX-GP  [C603H38]  72.85 52.31 0 top
C2602  SCD1U10V2KX-5GP  [C402H22]  72.73 54.09 270 top
C2603  SC2200P50V2KX-2GP  [C402H22]  86.47 153.3 90 bottom
C2604  SC4D7U6D3V3KX-GP  [C603H36]  86.6 152.16 90 bottom
C2605  SCD1U10V2KX-5GP  [C402H22]  89.26 159.14 270 bottom
C2606  SC470P50V3JN-2GP  [C603H36]  75.52 52.56 90 top
C2607  SC2200P50V2KX-2GP  [C402H22]  75.39 53.71 90 top
C2608  SCD1U10V2KX-5GP  [C402H22]  75.12 62.39 270 top
C2609  SCD1U10V2KX-5GP  [C402H22]  76.89 62.39 90 top
C2610  SCD1U10V2KX-5GP  [C402H22]  80.22 55.54 270 top
C2611  SC4D7U6D3V3KX-GP  [C603H36]  89.01 158 270 bottom
C2615  SCD1U10V2KX-5GP  [C402H22]  153.91 132.22 270 top
C2616  SC100P50V2JN-3GP  [C402H22]  151.32 133.23 0 top
C2701  SC4D7U6D3V3KX-GP  [C603H36]  161.27 7.88 180 bottom
C2702  SC4D7U6D3V3KX-GP  [C603H36]  161.91 14.16 0 bottom
C2703  SC1U10V2KX-1GP  [C402H22]  161.78 10.04 180 bottom
C2704  SC1U10V2KX-1GP  [C402H22]  159.75 10.42 90 top
C2705  SC2D2U6D3V2MX-GP  [C402H22]  162.31 13.85 270 top
C2706  SC4D7U6D3V3KX-GP  [C603H36]  158.22 5.85 180 bottom
C2707  SCD1U10V2KX-5GP  [C402H22]  155.18 10.42 180 top
C2708  SC4D7U6D3V3KX-GP  [C603H36]  152.51 7.66 90 bottom
C2709  SCD1U10V2KX-5GP  [C402H22]  156.57 10.17 180 top
C2710  SCD1U10V2KX-5GP  [C402H22]  162.03 16.27 180 top
C2711  SC4D7U6D3V3KX-GP  [C603H36]  161.91 16.52 0 bottom
C2712  SC10U6D3V3MX-GP  [C603H38]  161.4 5.98 90 bottom
C2713  SC10U6D3V3MX-GP  [C603H38]  157.84 18.68 0 bottom
C2715  SC4D7U6D3V3KX-GP  [C603H36]  159.49 5.85 180 bottom
C2716  SC4D7U6D3V3KX-GP  [C603H36]  150.48 10.3 0 bottom
C2717  SCD1U10V2KX-5GP  [C402H22]  151.62 10.17 0 bottom
C2718  SC4D7U6D3V3KX-GP  [C603H36]  151.62 15.28 0 bottom
C2719  SCD1U10V2KX-5GP  [C402H22]  151.49 17.54 270 top
C2720  SCD1U10V2KX-5GP  [C402H22]  154.92 22.36 0 top
C2723  SC22P50V2JN-4GP  [C402H22]  101.45 143.27 90 bottom
C2901  SC10U6D3V3MX-GP  [C603H38]  154.41 20.2 270 bottom
C2907  SC10U6D3V3MX-GP  [C603H38]  160.64 18.68 0 bottom
C2908  SC10U6D3V3MX-GP  [C603H38]  159.24 18.68 0 bottom
C3001  SC15P50V2JN-2-GP  [C402H22]  50.34 174.21 90 top
C3002  SCD1U10V2KX-5GP  [C402H22]  52.36 173.49 180 top
C3003  SCD1U10V2KX-4GP  [C402H20]  46.31 172.53 270 top
C3004  SC4D7U6D3V3KX-GP  [C603H36]  50.17 163.51 0 top
C3005  SC4D7U6D3V3KX-GP  [C603H36]  45.27 174.43 270 top
C3007  SCD1U10V2KX-4GP  [C402H20]  49.03 163.51 0 top
C3008  SCD1U10V2KX-4GP  [C402H20]  45.98 173.37 270 top
C3009  SCD1U10V2KX-5GP  [C402H22]  54.92 170.85 180 top
C3010  SC4D7U6D3V3KX-GP  [C603H36]  56 170.74 180 top
C3011  SC15P50V2JN-2-GP  [C402H22]  48.67 174.21 270 top
C3012  SC4D7U6D3V3KX-GP  [C603H36]  54.08 177 270 top
C3013  SCD1U10V2KX-5GP  [C402H22]  62.85 174.76 180 top
C3014  SCD1U10V2KX-5GP  [C402H22]  62.42 163.99 90 top
C3015  SC1U10V2KX-1GP  [C402H22]  62.21 172.35 0 top
C3016  SCD1U10V2KX-5GP  [C402H22]  62.42 164.85 90 top
C3017  SCD1U10V2KX-4GP  [C402H20]  47.25 163.51 0 top
C3018  SC1U10V2KX-1GP  [C402H22]  52.7 168.72 90 bottom
C3019  SCD1U10V2KX-4GP  [C402H20]  48.11 166.89 270 bottom
C3021  SCD1U10V2KX-4GP  [C402H20]  48.11 167.78 270 bottom
C3022  SCD1U10V2KX-4GP  [C402H20]  48.11 168.67 270 bottom
C3023  SCD1U10V2KX-4GP  [C402H20]  52.69 167.78 90 bottom
C3024  SCD1U10V2KX-4GP  [C402H20]  46.02 166.63 0 top
C3025  SCD1U10V2KX-4GP  [C402H20]  45.14 166.66 0 top
C3101  SC100P3KV8JN-2-GP  [C1808H56]  26.19 177.51 270 bottom
C3106  SCD01U50V2KX-1GP  [C402H22]  31.63 170.55 180 top
C3201  SC1U10V2KX-1GP  [C402H22]  16.75 14.62 0 bottom
C3202  SCD1U16V2KX-3GP  [C402H22]  12.02 21.91 90 bottom
C3203  SC4D7U6D3V3KX-GP  [C603H36]  11.92 20.43 90 bottom
C3204  SCD01U50V2KX-1GP  [C402H22]  22.56 15.5 180 bottom
C3205  SCD1U16V2KX-3GP  [C402H22]  11.79 19.34 90 bottom
C3206  SC1U10V2KX-1GP  [C402H22]  13.95 24.9 0 bottom
C3301  SCD1U16V2KX-3GP  [C402H22]  23.44 15.49 180 bottom
C3302  SC4D7U6D3V3KX-GP  [C603H36]  21.44 15.5 180 bottom
C3303  SC10U10V5KX-2GP  [C805H54]  14.18 22.62 0 bottom
C3401  SC4D7P50V2CN-1GP  [C402H22]  22.33 41.67 0 bottom
C3402  SC4D7P50V2CN-1GP  [C402H22]  22.33 39.89 180 bottom
C3403  SCD1U16V2KX-3GP  [C402H22]  27.67 42.94 180 bottom
C3404  SCD1U16V2KX-3GP  [C402H22]  26.78 42.94 180 bottom
C3405  SCD1U16V2KX-3GP  [C402H22]  21.8 37.3 90 bottom
C3406  SCD1U16V2KX-3GP  [C402H22]  155.18 42.94 90 bottom
C3505  SC1U10V3KX-3GP  [C603H36]  158.22 26.43 270 bottom
C3507  SCD1U10V2KX-5GP  [C402H22]  17.94 43.11 0 top
C3508  SC1U10V3KX-3GP  [C603H36]  20.61 43.11 180 bottom
C3510  SC1U10V3KX-3GP  [C603H36]  28.43 68.84 0 bottom
C3512  SC22U6D3V5MX-2GP  [C805H58]  18.9 43.19 180 bottom
C3513  SC22U6D3V5MX-2GP  [C805H58]  20.17 43.37 0 top
C3519  SCD1U16V2KX-3GP  [C402H22]  161.91 31.25 0 top
C3520  SC1U10V2KX-1GP  [C402H22]  161.02 31.25 0 top
C3521  SC22U6D3V5MX-2GP  [C805H58]  161.78 35.32 0 bottom
C3601  SC1KP50V2KX-1GP  [C402H22]  38.91 14.27 0 top
C3602  SC1KP50V2KX-1GP  [C402H22]  39.79 14.27 0 top
C3603  SC10U6D3V3MX-GP  [C603H38]  35.95 15.24 0 top
C3605  SC10U6D3V3MX-GP  [C603H38]  42.7 17.87 180 top
C3607  SC1U10V2KX-1GP  [C402H22]  150.86 26.17 0 top
C3612  SC1U10V2KX-1GP  [C402H22]  150.86 24.39 180 top
C3613  SC1U10V2KX-1GP  [C402H22]  149.08 78.88 270 bottom
C3617  SC1U10V2KX-1GP  [C402H22]  149.08 76.08 270 bottom
C3618  SC1KP50V2KX-1GP  [C402H22]  141.08 75.7 90 bottom
C3619  SC1KP50V2KX-1GP  [C402H22]  141.08 76.59 90 bottom
C3620  SC10U6D3V3MX-GP  [C603H38]  141.46 79.13 180 bottom
C3621  SC10U6D3V3MX-GP  [C603H38]  142.22 74.56 270 bottom
C3625  SCD1U10V2KX-5GP  [C402H22]  156.83 77.73 0 bottom
C3626  SCD1U10V2KX-5GP  [C402H22]  150.93 78.04 270 bottom
C5201  SCD1U10V2KX-5GP  [C402H22]  97.19 153.48 0 top
C5202  SC1KP50V2KX-1GP  [C402H22]  97.9 157.74 180 top
C5203  SCD1U10V2KX-5GP  [C402H22]  78.98 155.79 90 top
C5204  SC4D7U6D3V3KX-GP  [C603H36]  103.23 149.62 0 top
C5205  SCD1U25V3KX-GP  [C603H36]  99.04 157.74 0 top
C5206  SC1U6D3V2KX-GP  [C402H22]  98.08 153.48 180 top
C5207  SC4D7U6D3V3KX-GP  [C603H36]  92.74 142.38 0 bottom
C5208  SC10P50V2JN-4GP  [C402H22]  98.53 137.68 90 top
C5209  SCD1U10V2KX-5GP  [C402H22]  78.85 156.86 90 top
C5210  SCD1U10V2KX-5GP  [C402H22]  78.98 154.98 90 top
C5211  SCD1U10V2KX-5GP  [C402H22]  80.86 153.38 90 top
C5212  SCD1U10V2KX-5GP  [C402H22]  78.85 157.74 90 top
C5213  SCD1U10V2KX-5GP  [C402H22]  80.86 152.49 90 top
C5214  SC10P50V2JN-4GP  [C402H22]  98.53 135.9 90 top
C5401  SCD1U16V2KX-3GP  [C402H22]  18.9 72.53 90 top
C5402  SCD1U10V2KX-5GP  [C402H22]  22.41 75.68 90 bottom
C5403  SCD1U10V2KX-5GP  [C402H22]  22.41 74.86 90 bottom
C5404  SCD1U10V2KX-5GP  [C402H22]  22.41 77.33 90 bottom
C5405  SCD1U10V2KX-5GP  [C402H22]  22.41 76.52 90 bottom
C5406  SCD1U10V2KX-5GP  [C402H22]  22.49 73.06 90 bottom
C5407  SCD1U10V2KX-5GP  [C402H22]  22.49 72.25 90 bottom
C5408  SCD1U10V2KX-5GP  [C402H22]  22.49 71.44 90 bottom
C5409  SCD1U10V2KX-5GP  [C402H22]  22.49 73.87 90 bottom
C5506  SC10P50V2JN-4GP  [C402H22]  24.87 58.3 0 top
C5508  SC100P50V2JN-L-GP  [C402H22]  27.64 64.17 0 top
C5509  SC18P50V2JN-1-GP  [C402H22]  25.25 68.36 90 top
C5510  SC18P50V2JN-1-GP  [C402H22]  23.55 68.36 270 top
C5511  SC100P50V2JN-L-GP  [C402H22]  27.64 65.85 180 top
C5519  SCD01U16V2KX-3GP  [C402H22]  18.9 71.64 90 top
C5539  SC10P50V2JN-4GP  [C402H22]  24.87 61.22 180 top
C5540  SC10P50V2JN-4GP  [C402H22]  24.87 64.02 180 top
C5541  SC10P50V2JN-4GP  [C402H22]  21.57 58.3 0 top
C5542  SC10P50V2JN-4GP  [C402H22]  21.57 61.35 180 top
C5543  SC10P50V2JN-4GP  [C402H22]  21.57 64.02 180 top
C5601  SC10U10V5KX-2GP  [C805H54]  170.42 81.29 180 bottom
C5602  SCD01U50V2KX-1GP  [C402H22]  158.86 32.4 90 bottom
C5603  SCD01U50V2KX-1GP  [C402H22]  158.86 33.28 90 bottom
C5604  SCD1U16V2KX-3GP  [C402H22]  168.1 79.89 180 bottom
C5605  SC10U10V5KX-2GP  [C805H54]  164.22 35.89 90 bottom
C5606  SCD1U16V2KX-3GP  [C402H22]  163.94 34.48 90 bottom
C5607  SCD01U50V2KX-1GP  [C402H22]  160.26 78.62 270 top
C5608  SCD01U50V2KX-1GP  [C402H22]  160.26 79.51 270 top
C5609  SC10U10V5KX-2GP  [C805H54]  166.15 80.76 90 bottom
C5610  SC10U10V5KX-2GP  [C805H54]  170.06 88.86 0 bottom
C5611  SCD01U50V2KX-1GP  [C402H22]  160.26 77.73 270 top
C5612  SCD01U50V2KX-1GP  [C402H22]  160.26 76.85 270 top
C5615  SCD01U50V2KX-1GP  [C402H22]  158.86 35.06 270 bottom
C5616  SCD01U50V2KX-1GP  [C402H22]  158.86 34.17 270 bottom
C5801  SCD1U16V2KX-3GP  [C402H22]  162.72 67.42 270 top
C5802  SCD1U16V2KX-3GP  [C402H22]  161.91 8.01 180 top
C5803  SCD1U16V2KX-3GP  [C402H22]  169.91 40.4 90 bottom
C5804  SCD1U16V2KX-3GP  [C402H22]  169.91 66.3 0 bottom
C5805  SC10U6D3V3MX-GP  [C603H38]  163 66.36 270 top
C5806  SC10U6D3V3MX-GP  [C603H38]  169.91 41.54 90 bottom
C6202  SCD1U10V2KX-5GP  [C402H22]  58.91 73.04 270 top
C6203  SCD1U10V2KX-5GP  [C402H22]  161.75 128.03 270 top
C6204  SCD1U10V2KX-5GP  [C402H22]  161.4 121.42 0 top
C6205  SCD1U16V2KX-3GP  [C402H22]  169.22 149.44 0 bottom
CARD1  CARDBUS11P-SKT-8-GP  [CS1S-461HN]  22.1 16.87 270 top
CN6301  PTWO-CON24-6-GP  [196246-24021]  169.3 33.27 90 top
CPU1  BEEMA-GP  [BGA769M24D5H78]  117.8 85.48 270 bottom
D401  LBAS16LT1G-GP  [SOT23-2D4-312H44]  86.72 85.1 0 bottom
D2401  RB751V-40H-GP  [SOD323AKH38]  153.54 148.31 180 bottom
D2501  BAS40-05-7-F-1-GP  [SOT23-2D4-312H48]  65.13 15.89 180 bottom
D2601  RB551V30-GP  [SOD323AKH38]  88.37 154.95 0 bottom
D2701  BAT54CPT-2-GP  [SOT23-2D6-312H46]  154.79 25.16 0 bottom
D3602  LBAS16LT1G-GP  [SOT23-2D4-312H44]  161.81 143.27 0 top
D3603  BAS16-6-GP  [SOT23-2D4-312H44]  152.13 74.69 270 bottom
D3606  RB751V-40H-GP  [SOD323AKH38]  155.23 74.56 0 bottom
D4301  LBAV99LT1G-1-GP  [SOT23-2D4-312H44]  135.87 175.02 180 top
D4302  LBAV99LT1G-1-GP  [SOT23-2D4-312H44]  144 175.02 180 top
D4303  LBAV99LT1G-1-GP  [SOT23-2D4-312H44]  140.06 175.02 180 top
D5201  BAT54CPT-2-GP  [SOT23-2D6-312H46]  105.26 158.32 180 top
D5202  RB551V30-GP  [SOD323AKH38]  102.98 144.79 90 bottom
D5401  BAW56-5-GP  [SOT-23-9H44]  35.36 79.23 90 bottom
D5501  RB551V30-GP  [SOD323AKH38]  27.29 74.18 90 top
DB1  ACES-CON10-14-GP  [87212-1002N]  169.76 136.15 270 top
DCIN1  ACES-CON6-63-GP  [50458-00601-W01]  97.55 166.77 180 top
DM1  DDR3-204P-108-GP-U  [80001-1921]  107.9 34.07 180 bottom
DM2  DDR3-204P-259-GP  [AS0A621-J4SB-7H]  112.8 20.87 0 bottom
EC2501  SC4D7P50V2CN-1GP  [C402H22]  150.98 122.06 270 bottom
EC2502  SC4D7P50V2CN-1GP  [C402H22]  140.27 105.14 180 top
EC2503  SC10P50V2JN-4GP  [C402H22]  150.2 123.1 0 top
EC2601  SCD1U10V2KX-5GP  [C402H22]  86.47 154.19 90 bottom
EC2602  SC10P50V2JN-4GP  [C402H22]  96.76 150 180 bottom
EC2701  SC10P50V2JN-4GP  [C402H22]  102.72 141.11 180 bottom
EC2703  SCD1U10V2KX-5GP  [C402H22]  161.02 4.2 180 bottom
EC2704  SC1KP50V2KX-1GP  [C402H22]  158.05 15.12 0 top
EC2705  SCD1U10V2KX-5GP  [C402H22]  158.35 10.42 180 top
EC2706  SC1KP50V2KX-1GP  [C402H22]  158.99 13.78 270 top
EC2707  SC1KP50V2KX-1GP  [C402H22]  158.99 12.05 270 top
EC2708  SCD1U10V2KX-5GP  [C402H22]  150.48 16.97 180 bottom
EC2709  SCD1U10V2KX-5GP  [C402H22]  150.48 15.19 0 bottom
EC2901  SC2K2P50V3KX-GP  [C603]  60.31 12.46 0 bottom
EC2902  SC2K2P50V3KX-GP  [C603]  58.78 9.41 180 bottom
EC2903  SC2K2P50V3KX-GP  [C603]  60.18 8.01 0 bottom
EC2904  SC2K2P50V3KX-GP  [C603]  60.18 4.71 180 bottom
EC2905  SC100P50V2JN-3GP  [C402H22]  156.95 22.62 270 top
EC2906  SC100P50V2JN-3GP  [C402H22]  156.95 23.63 270 top
EC2907  SC100P50V2JN-3GP  [C402H22]  164.57 8.65 0 top
EC2908  SC100P50V2JN-3GP  [C402H22]  165.08 7.38 90 top
EC3101  SC10P50V2JN-4GP  [C402H22]  39.22 170.7 0 bottom
EC3102  SC10P50V2JN-4GP  [C402H22]  39.22 172.48 180 bottom
EC3103  SC10P50V2JN-4GP  [C402H22]  39.22 174.25 0 bottom
EC3104  SC10P50V2JN-4GP  [C402H22]  39.22 176.03 180 bottom
EC3105  SC10P50V2JN-4GP  [C402H22]  38.84 176.03 0 top
EC3106  SC10P50V2JN-4GP  [C402H22]  38.84 174.25 180 top
EC3107  SC10P50V2JN-4GP  [C402H22]  38.84 172.48 0 top
EC3108  SC10P50V2JN-4GP  [C402H22]  38.84 170.7 180 top
EC3201  SC6P50V2CN-1GP  [C402H22]  29.06 20.84 180 top
EC3301  SC4D7P50V2BN-GP  [C402H22]  29.06 24.39 90 top
EC3302  SC4D7P50V2BN-GP  [C402H22]  28.56 7.94 180 top
EC3303  SC4D7P50V2BN-GP  [C402H22]  28.53 10.5 180 top
EC3304  SC4D7P50V2BN-GP  [C402H22]  28.53 12.23 180 top
EC3305  SC4D7P50V2BN-GP  [C402H22]  29.06 26.81 90 top
EC3306  SC4D7P50V2BN-GP  [C402H22]  29.06 22.87 90 top
EC3307  SC4D7P50V2BN-GP  [C402H22]  27.54 30.62 90 top
EC4201  SCD1U25V2KX-GP  [C402H22]  109.2 162.7 180 bottom
EC4202  SC10U25V5KX-GP  [C805H56]  107.8 162.95 180 bottom
EC4203  SCD1U50V5JX-1-GP  [C805H38]  109.84 161.55 90 top
EC4301  SC10P50V2JN-4GP  [C402H22]  137.14 177.56 270 top
EC4302  SC10P50V2JN-4GP  [C402H22]  138.92 177.56 90 top
EC4303  SCD1U25V2KX-GP  [C402H22]  163.38 170.37 90 top
EC4304  SCD1U25V3KX-GP  [C603H36]  163.23 169.28 90 top
EC4305  SC10P50V2JN-4GP  [C402H22]  143.75 177.56 270 top
EC4401  SC2200P50V2KX-2GP  [C402H22]  144.63 155.46 0 top
EC4402  SCD1U25V2KX-GP  [C402H22]  144.63 155.46 180 bottom
EC4601  SCD1U25V3KX-GP  [C603H36]  68.43 18.3 0 top
EC5205  SC22P50V2JN-4GP  [C402H22]  100.18 141.11 180 bottom
EC5206  SC22P50V2JN-4GP  [C402H22]  100.18 142.89 0 bottom
EC5210  SC33P50V2JN-3GP  [C402H22]  93.81 142.23 0 bottom
EC5801  SC33P50V2JN-3GP  [C402H22]  160.64 49.92 180 bottom
EC5802  SC33P50V2JN-3GP  [C402H22]  160.64 51.7 0 bottom
EC6101  SC1KP50V2KX-1GP  [C402H22]  167.27 163.66 90 bottom
EC6103  SC220P50V2KX-3GP  [C402H22]  45.32 5.47 180 top
EC6105  SC220P50V2KX-3GP  [C402H22]  42.78 5.47 180 top
EC6106  SCD1U16V2KX-3GP  [C402H22]  32.11 7.76 90 top
EC6107  SCD1U16V2KX-3GP  [C402H22]  170.19 168.24 270 bottom
EC6205  SC33P50V2JN-3GP  [C402H22]  54.59 79.51 180 top
EC6206  SC33P50V2JN-3GP  [C402H22]  55.86 73.92 0 top
EC6207  SC33P50V2JN-3GP  [C402H22]  55.86 75.7 180 top
EC6208  SC33P50V2JN-3GP  [C402H22]  54.59 77.73 0 top
EC9701  SCD1U25V2KX-GP  [C402H22]  112.5 164.07 90 bottom
EC9703  SCD1U25V2KX-GP  [C402H22]  126.98 173.11 0 bottom
EC9704  SCD1U25V2KX-GP  [C402H22]  130.16 151.14 0 bottom
EC9705  SCD1U25V2KX-GP  [C402H22]  142.35 160.16 270 bottom
EC9707  SC1KP50V2KX-1GP  [C402H22]  142.22 126.63 90 top
EC9708  SCD1U25V2KX-GP  [C402H22]  102.85 139.46 90 bottom
EC9709  SC1KP50V2KX-1GP  [C402H22]  108.62 153.91 90 bottom
EC9710  SC1KP50V2KX-1GP  [C402H22]  33.51 53.48 90 top
EC9711  SC1KP50V2KX-1GP  [C402H22]  133.08 172.35 180 top
EC9712  SCD1U25V2KX-GP  [C402H22]  149.46 111.14 270 bottom
EC9713  SCD1U25V2KX-GP  [C402H22]  133.84 143.01 180 bottom
EC9714  SC1KP50V2KX-1GP  [C402H22]  67.67 67.57 270 top
EC9715  SCD1U25V2KX-GP  [C402H22]  135.87 139.58 270 top
EC9716  SCD1U25V2KX-GP  [C402H22]  104.5 154.7 180 bottom
EC9717  SCD1U25V2KX-GP  [C402H22]  112.5 164.91 90 bottom
EC9718  SC1U6D3V2KX-GP  [C402H22]  45.24 17.54 90 top
EC9719  SC1U6D3V2KX-GP  [C402H22]  165.59 18.55 90 top
EC9720  SC1U6D3V2KX-GP  [C402H22]  145.02 11.19 180 top
EC9721  SC1U6D3V2KX-GP  [C402H22]  145.9 11.19 180 top
EC9722  SC1U6D3V2KX-GP  [C402H22]  41.64 18.02 180 top
EC9723  SC1U6D3V2KX-GP  [C402H22]  166.14 79.39 90 bottom
EC9724  SC1U6D3V2KX-GP  [C402H22]  87.61 139.96 180 bottom
EC9725  SC1U6D3V2KX-GP  [C402H22]  27.9 76.9 90 top
EC9726  SC1U6D3V2KX-GP  [C402H22]  157.59 37.22 0 top
EC9727  SC1U6D3V2KX-GP  [C402H22]  45.24 15.91 90 top
EC9728  SC1U6D3V2KX-GP  [C402H22]  161.04 118.96 90 bottom
EC9732  SC1U6D3V2KX-GP  [C402H22]  44.7 19.16 0 top
EC9733  SC1U6D3V2KX-GP  [C402H22]  50.78 24.01 270 bottom
EC9734  SC1U6D3V2KX-GP  [C402H22]  45.59 19.16 0 top
EC9735  SC1U6D3V2KX-GP  [C402H22]  91.17 143.01 270 bottom
EC9736  SC1U6D3V2KX-GP  [C402H22]  105.44 152.74 180 top
EC9737  SC1U6D3V2KX-GP  [C402H22]  162.71 68.26 270 top
EC9738  SC1U6D3V2KX-GP  [C402H22]  37.47 15.53 0 top
EC9739  SCD1U10V2KX-5GP  [C402H22]  164.07 18.43 270 bottom
EC9740  SCD1U25V2KX-GP  [C402H22]  73.64 67.57 90 top
EC9741  SCD1U25V2KX-GP  [C402H22]  117.84 158.89 270 bottom
EC9742  SCD1U25V2KX-GP  [C402H22]  152.38 171.46 180 top
EC9743  SCD1U10V2KX-5GP  [C402H22]  167.62 20.33 270 bottom
EC9744  SCD1U10V2KX-5GP  [C402H22]  156.57 25.03 180 top
EC9745  SC1KP50V2KX-1GP  [C402H22]  157.21 15.12 0 top
EC9746  SCD1U25V2KX-GP  [C402H22]  71.74 18.81 90 bottom
EC9747  SCD1U25V2KX-GP  [C402H22]  153.27 171.46 180 top
EC9748  SCD1U25V2KX-GP  [C402H22]  151.49 171.46 180 top
EC9749  SCD1U25V2KX-GP  [C402H22]  105.39 154.7 180 bottom
EC9750  SCD1U25V2KX-GP  [C402H22]  116.44 23.51 90 top
EC9751  SCD1U25V2KX-GP  [C402H22]  69.7 30.24 270 top
EC9752  SCD1U25V2KX-GP  [C402H22]  108.95 74.18 270 top
EC9753  SCD1U25V2KX-GP  [C402H22]  114.66 37.22 90 top
EC9754  SCD1U25V2KX-GP  [C402H22]  118.47 42.43 90 top
EC9755  SCD1U25V2KX-GP  [C402H22]  114.66 36.33 90 top
EC9756  SCD1U25V2KX-GP  [C402H22]  74.66 18.43 0 top
EC9757  SCD1U25V2KX-GP  [C402H22]  126.73 73.67 90 top
EC9758  SCD1U25V2KX-GP  [C402H22]  89.52 50.56 270 top
EC9759  SC1U6D3V2KX-GP  [C402H22]  143.21 42.66 270 top
EC9760  SC1U6D3V2KX-GP  [C402H22]  33.69 15.28 0 top
EC9761  SC1U6D3V2KX-GP  [C402H22]  18.83 58.35 180 bottom
EC9762  SC1U6D3V2KX-GP  [C402H22]  164.42 145.5 90 top
ED2401  AZ5325-01FDR7G-GP  [D402H24]  150.4 141.11 90 top
ED2402  AZ5325-01FDR7G-GP  [D402H24]  152.05 144.26 0 top
ED2403  AZ5325-01FDR7G-GP  [D402H24]  157.18 144.94 270 top
ED6101  AZ5725-01FDR7G-GP  [SOD882-10D6-1H20]  167.29 164.53 90 bottom
EL4201  PAD-2P-4516-GP-U  [PAD-2P-4516-U]  93.96 166.38 180 bottom
EL4202  PAD-2P-4516-GP-U  [PAD-2P-4516-U]  91.29 166.38 180 bottom
EL4203  PAD-2P-4516-GP-U  [PAD-2P-4516-U]  109.07 157.74 180 top
EU3403  AZC099-04S-1-GP  [SOT-6H58]  20.82 39.17 270 top
EU3404  AZC099-04S-1-GP  [SOT-6H58]  158.99 42.05 270 bottom
EU5602  AZ1045-04F-R7G-GP  [DFN10G2510H26]  163.3 29.73 270 bottom
F5201  POLYSW-1D1A24V-GP-U  [POLYSW-4633-UH43]  101.1 156.53 90 bottom
F5203  POLYSW-1D1A24V-GP-U  [POLYSW-4633-UH43]  92.94 138.12 180 bottom
F5501  POLYSW-1D1A6V-9-GP-U  [POLYSW-2114H30]  19.67 69.48 90 top
F6201  POLYSW-D5A6V-1-GP  [POLYSW-2114H50]  163.43 121.04 0 bottom
FAN1  ETY-CON3-8-GP  [3703K-Q03N-11L]  90.3 148.37 90 bottom
FAN261  APL5606AKI-TRG-GP  [SOIC8H69]  83.55 157.62 270 bottom
G701  GAP-OPEN  [CON2O-U]  134.6 95.13 0 top
G6101  GAP-OPEN  [CON2O-U]  167.27 167.27 270 bottom
G6102  GAP-OPEN  [CON2O-U]  167.27 165.75 270 bottom
H1  HOLE256R126-1-GP  [HOLE256R126]  141.7 165.77 0 top
H2  HOLE335R115-GP  [HOLE335R115]  169.3 12.77 0 top
H3  HOLE335R115-GP  [HOLE335R115]  20.3 50.77 0 top
H4  HOLE335R115-GP  [HOLE335R115]  37.4 164.77 180 bottom
H5  HOLE335R115-GP  [HOLE335R115]  96.3 128.47 0 top
H7  HOLE296R182-GP  [HOLE296R182]  153.9 60.97 0 top
HDA27  ALC3234-CG-GP  [QFN48J6-G465H40]  156.55 12.71 270 bottom
HDD1  STAR-CON12-1-GP  [132F12-010000-A2-R]  170.8 30.88 270 bottom
HDLED1  LED-W-27-GP-U  [LED3015-1A2K-3PH44]  17.7 1.47 90 top
HDMI1  PAD-D-SUB-HDMI-COLAY-GP-U  [PAD-D-SUB-HDMI-COLAY-U]  4.15 65.22 90 bottom
HDT1  SMC-CONN20A-1-GP  [ASP-137098-05]  94.85 84.08 90 bottom
KB1  ACES-CON30-10-GP  [FL4S030HT6R300-DT]  159.3 104.55 270 top
KBC24  NPCE285PA0DX-GP  [LQFP128H63]  154.02 135.67 180 bottom
KBLIT1  ACES-CON4-56-GP-U  [51575-00401-W01]  168.65 123.07 90 top
L3001  IND-4D7UH-242-GP  [L2520-D820H41]  54.48 174.33 180 top
L5507  BLM18BB220SN-GP  [L1608-UH38]  23.22 58.68 270 top
L5508  BLM18BB220SN-GP  [L1608-UH38]  23.22 63.64 270 top
L5509  BLM18BB220SN-GP  [L1608-UH38]  23.22 60.84 270 top
LCD1  ACES-CON40-18-GP  [51540-04001-W01]  91.05 146.77 270 top
LED1  LED-YW-5-GP  [LED3020-3P-19H44]  22.7 1.97 90 top
LOM30  RTL8111G-CGT-1-GP-U2  [QFN32J4-G2D85H36]  50.27 169.3 90 top
NOREF  *  [unnamed]  176.98 185.02 0 top
NOREF#2  -  [unnamed]  13.15 -4.43 0 top
NOREF#3  -  [#2]  76.32 -7.8 0 top
NOREF#4  -  [unnamed]  5.8 79.07 270 top
NOREF#5  -  [#2]  95.49 9.66 0 top
NOREF#6  *  [unnamed]  160.83 -1.74 0 top
NOREF#7  *  [unnamed]  170.29 155.71 0 top
NOREF#8  *  [unnamed]  170.67 6.79 0 top
NOREF#9  -  [unnamed]  148.1 163.97 0 top
NOREF#10  -  [#2]  4.3 -23.23 0 top
NOREF#11  -  [#2]  156.95 157.36 0 top
NOREF#12  -  [unnamed]  168.13 3.54 0 top
NOREF#13  *  [unnamed]  54.03 5.68 0 top
NOREF#14  *  [unnamed]  60.31 177.61 0 top
NOREF#15  -  [#2]  4.3 -23.23 0 top
NOREF#16  -  [unnamed]  31.26 186.83 0 top
NOREF#17  -  [unnamed]  175.18 187.78 0 top
NOREF#18  -  [#2]  136.38 54.37 0 top
NOREF#19  *  [unnamed]  16.05 183.93 0 top
NOREF#20  -  [unnamed]  137.33 188.02 0 top
NOREF#21  -  [unnamed]  1.39 187.69 0 top
NOREF#22  -  [#2]  123.68 176.41 0 top
NOREF#23  -  [#2]  -56.79 -6.36 0 top
NOREF#24  *  [unnamed]  13.77 79.94 0 top
NOREF#25  *  [unnamed]  16.05 183.93 180 bottom
NOREF#26  *  [unnamed]  60.31 177.61 180 bottom
NOREF#27  *  [unnamed]  176.98 185.02 180 bottom
NOREF#28  *  [unnamed]  13.77 79.94 180 bottom
NOREF#29  -  [#2]  131.17 176.54 180 bottom
NOREF#30  *  [unnamed]  54.03 5.68 180 bottom
NOREF#31  *  [unnamed]  160.83 -1.74 180 bottom
NOREF#32  *  [unnamed]  170.67 6.79 180 bottom
NOREF#33  *  [unnamed]  170.29 155.71 180 bottom
ODD1  ACES-CON20-30-GP-U  [51519-02001-W03]  171.3 81.32 90 top
PC4010  SCD47U25V3KX-1GP  [C603H36]  132.82 159.01 180 top
PC4201  SC1U50V5ZY-1-GP-U  [C805H58]  95.89 158.96 180 bottom
PC4202  SCD1U50V3KX-GP  [C603H36]  99.68 163.59 270 bottom
PC4203  SCD01U50V2KX-1GP  [C402H22]  113.39 174.51 180 top
PC4204  SCD01U50V2KX-1GP  [C402H22]  114.28 174.51 180 top
PC4205  SCD01U50V2KX-1GP  [C402H22]  115.17 174.51 180 top
PC4206  SC10U25V5KX-GP  [C805H56]  116.57 175.02 180 top
PC4208  SC1U25V3KX-1-GP  [C603H36]  78.98 159.01 90 top
PC4209  SCD01U50V2KX-1GP  [C402H22]  79.48 164.48 180 top
PC4210  SCD47U6D3V2KX-GP  [C402H22]  81.77 163.59 180 top
PC4401  SCD1U25V3KX-GP  [C603H36]  124.87 160.95 270 top
PC4402  SCD1U25V2KX-GP  [C402H22]  129.14 161.53 270 bottom
PC4403  SC1U25V3KX-1-GP  [C603H36]  130.28 160.39 270 bottom
PC4404  SC1U25V3KX-1-GP  [C603H36]  127.74 160.39 90 bottom
PC4406  SC10U25V5KX-GP  [C805H56]  143.24 155.33 0 top
PC4407  SC1U25V3KX-1-GP  [C603H36]  132.44 154.7 270 bottom
PC4408  SC4D7U25V5KX-GP  [C805H54]  143.24 155.33 180 bottom
PC4409  SCD1U50V3KX-GP  [C603H36]  141.59 155.46 180 bottom
PC4411  SCD047U25V2KX-GP  [C402H22]  134.22 156.6 180 top
PC4412  SCD01U50V2KX-1GP  [C402H22]  126.88 157.95 270 bottom
PC4413  SC3300P50V3KX-1GP  [C603H36]  133.08 156.6 0 top
PC4415  SC10U25V5KX-GP  [C805H56]  169.12 174.36 90 top
PC4416  SC10U25V5KX-GP  [C805H56]  162.29 167.14 0 top
PC4417  SC10U25V5KX-GP  [C805H56]  160.38 167.14 0 top
PC4418  SC10U25V5KX-GP  [C805H56]  169.12 172.45 90 top
PC4419  SCD1U50V3KX-GP  [C603H36]  169.17 176.03 90 top
PC4420  SCD1U25V2KX-GP  [C402H22]  128.51 152.92 0 bottom
PC4421  SCD1U25V2KX-GP  [C402H22]  128 151.65 90 bottom
PC4422  SC220P50V2JN-3GP  [C402H22]  126.88 156.17 270 bottom
PC4423  SCD1U25V2KX-GP  [C402H22]  127.62 152.92 0 bottom
PC4425  SCD01U50V2KX-1GP  [C402H22]  121.67 163.43 90 top
PC4426  SC10U25V5KX-GP  [C805H56]  141.33 155.33 0 top
PC4434  SC1U25V3KX-1-GP  [C603H36]  113.6 165.49 270 top
PC4503  SC4D7U25V5KX-GP  [C805H54]  34.02 49.16 270 bottom
PC4504  SC4D7U25V5KX-GP  [C805H54]  34.02 49.29 90 top
PC4505  SCD1U50V3KX-L-GP  [C603H36]  35.67 54.62 270 top
PC4506  SC18P50V2JN-1-GP  [C402H22]  38.46 58.43 0 top
PC4507  SC10U25V5KX-GP  [C805H56]  37.45 50.05 0 top
PC4508  SCD1U16V2KX-3GP  [C402H22]  35.8 26.93 270 bottom
PC4510  SCD1U50V3KX-L-GP  [C603H36]  44.81 54.75 270 top
PC4514  SC10U25V5KX-GP  [C805H56]  45.19 48.91 270 top
